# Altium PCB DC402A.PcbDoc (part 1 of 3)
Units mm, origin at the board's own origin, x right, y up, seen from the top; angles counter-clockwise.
Board outline 93 x 73 mm, 4 copper layers (Top Layer, Int1 (GND), Int2 (PWR), Bottom Layer), stack 1.369 mm thick; 244 components, 141 nets, 575 pads, 306 vias.
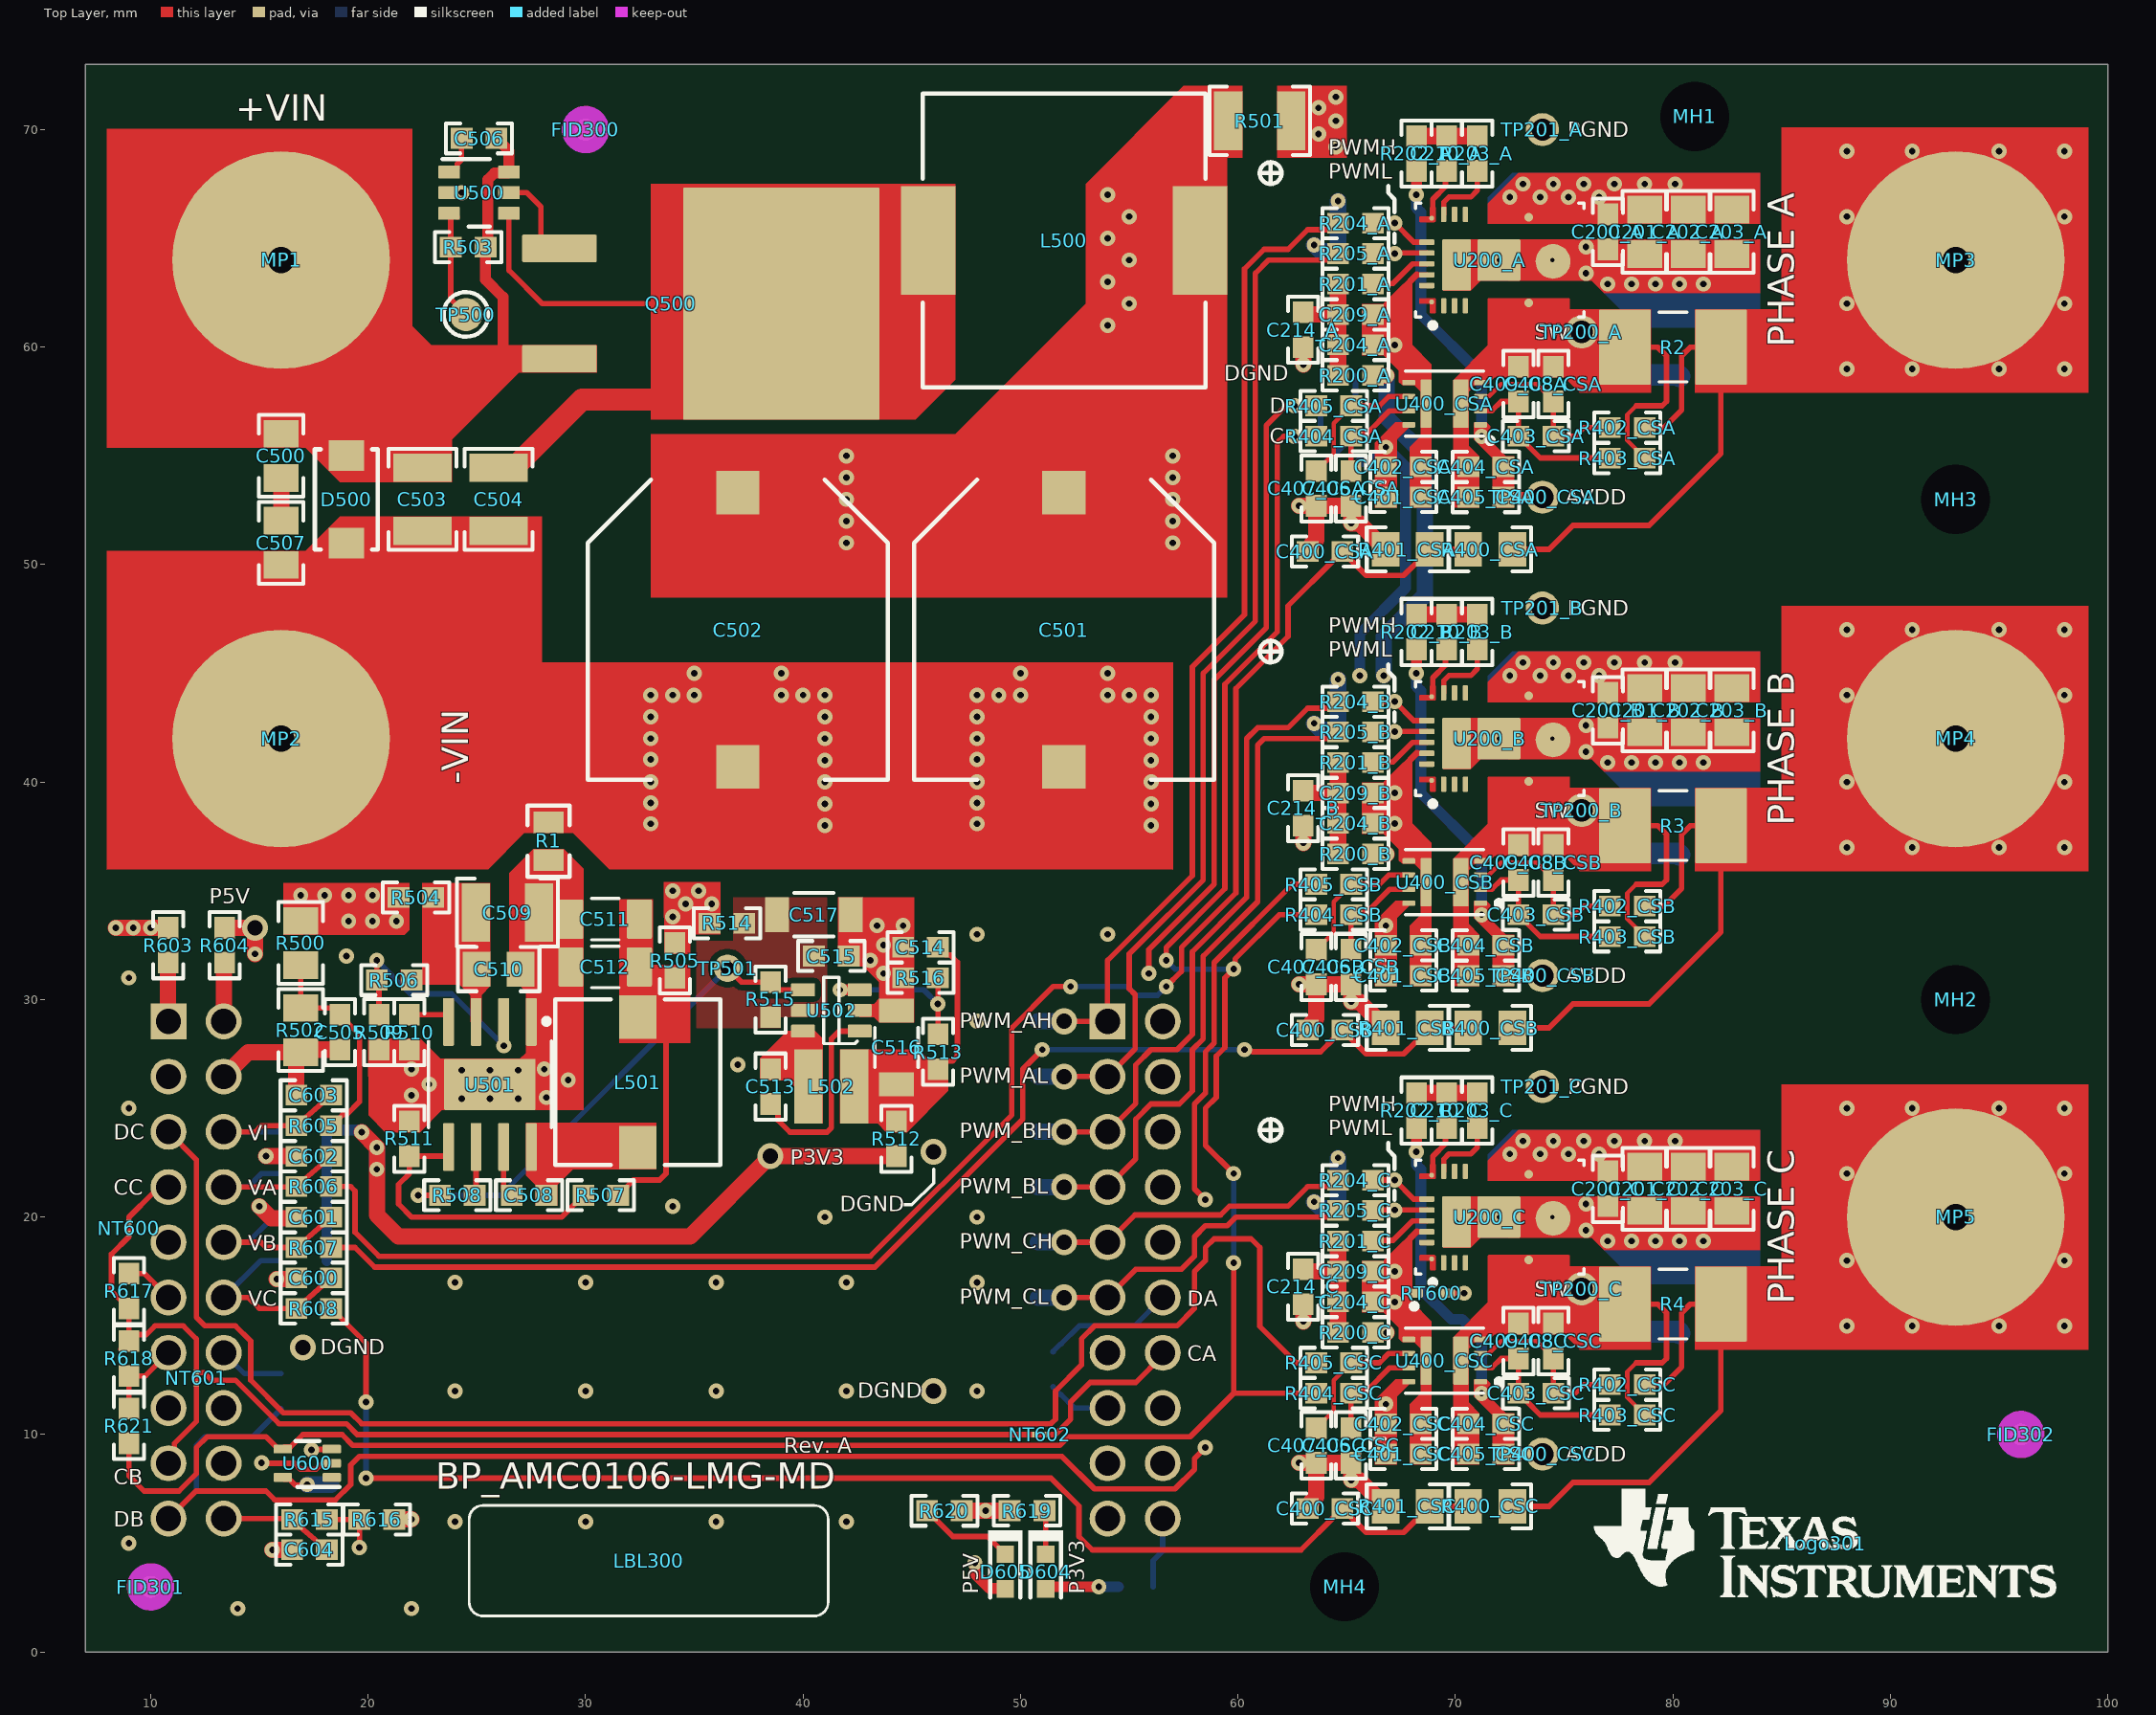
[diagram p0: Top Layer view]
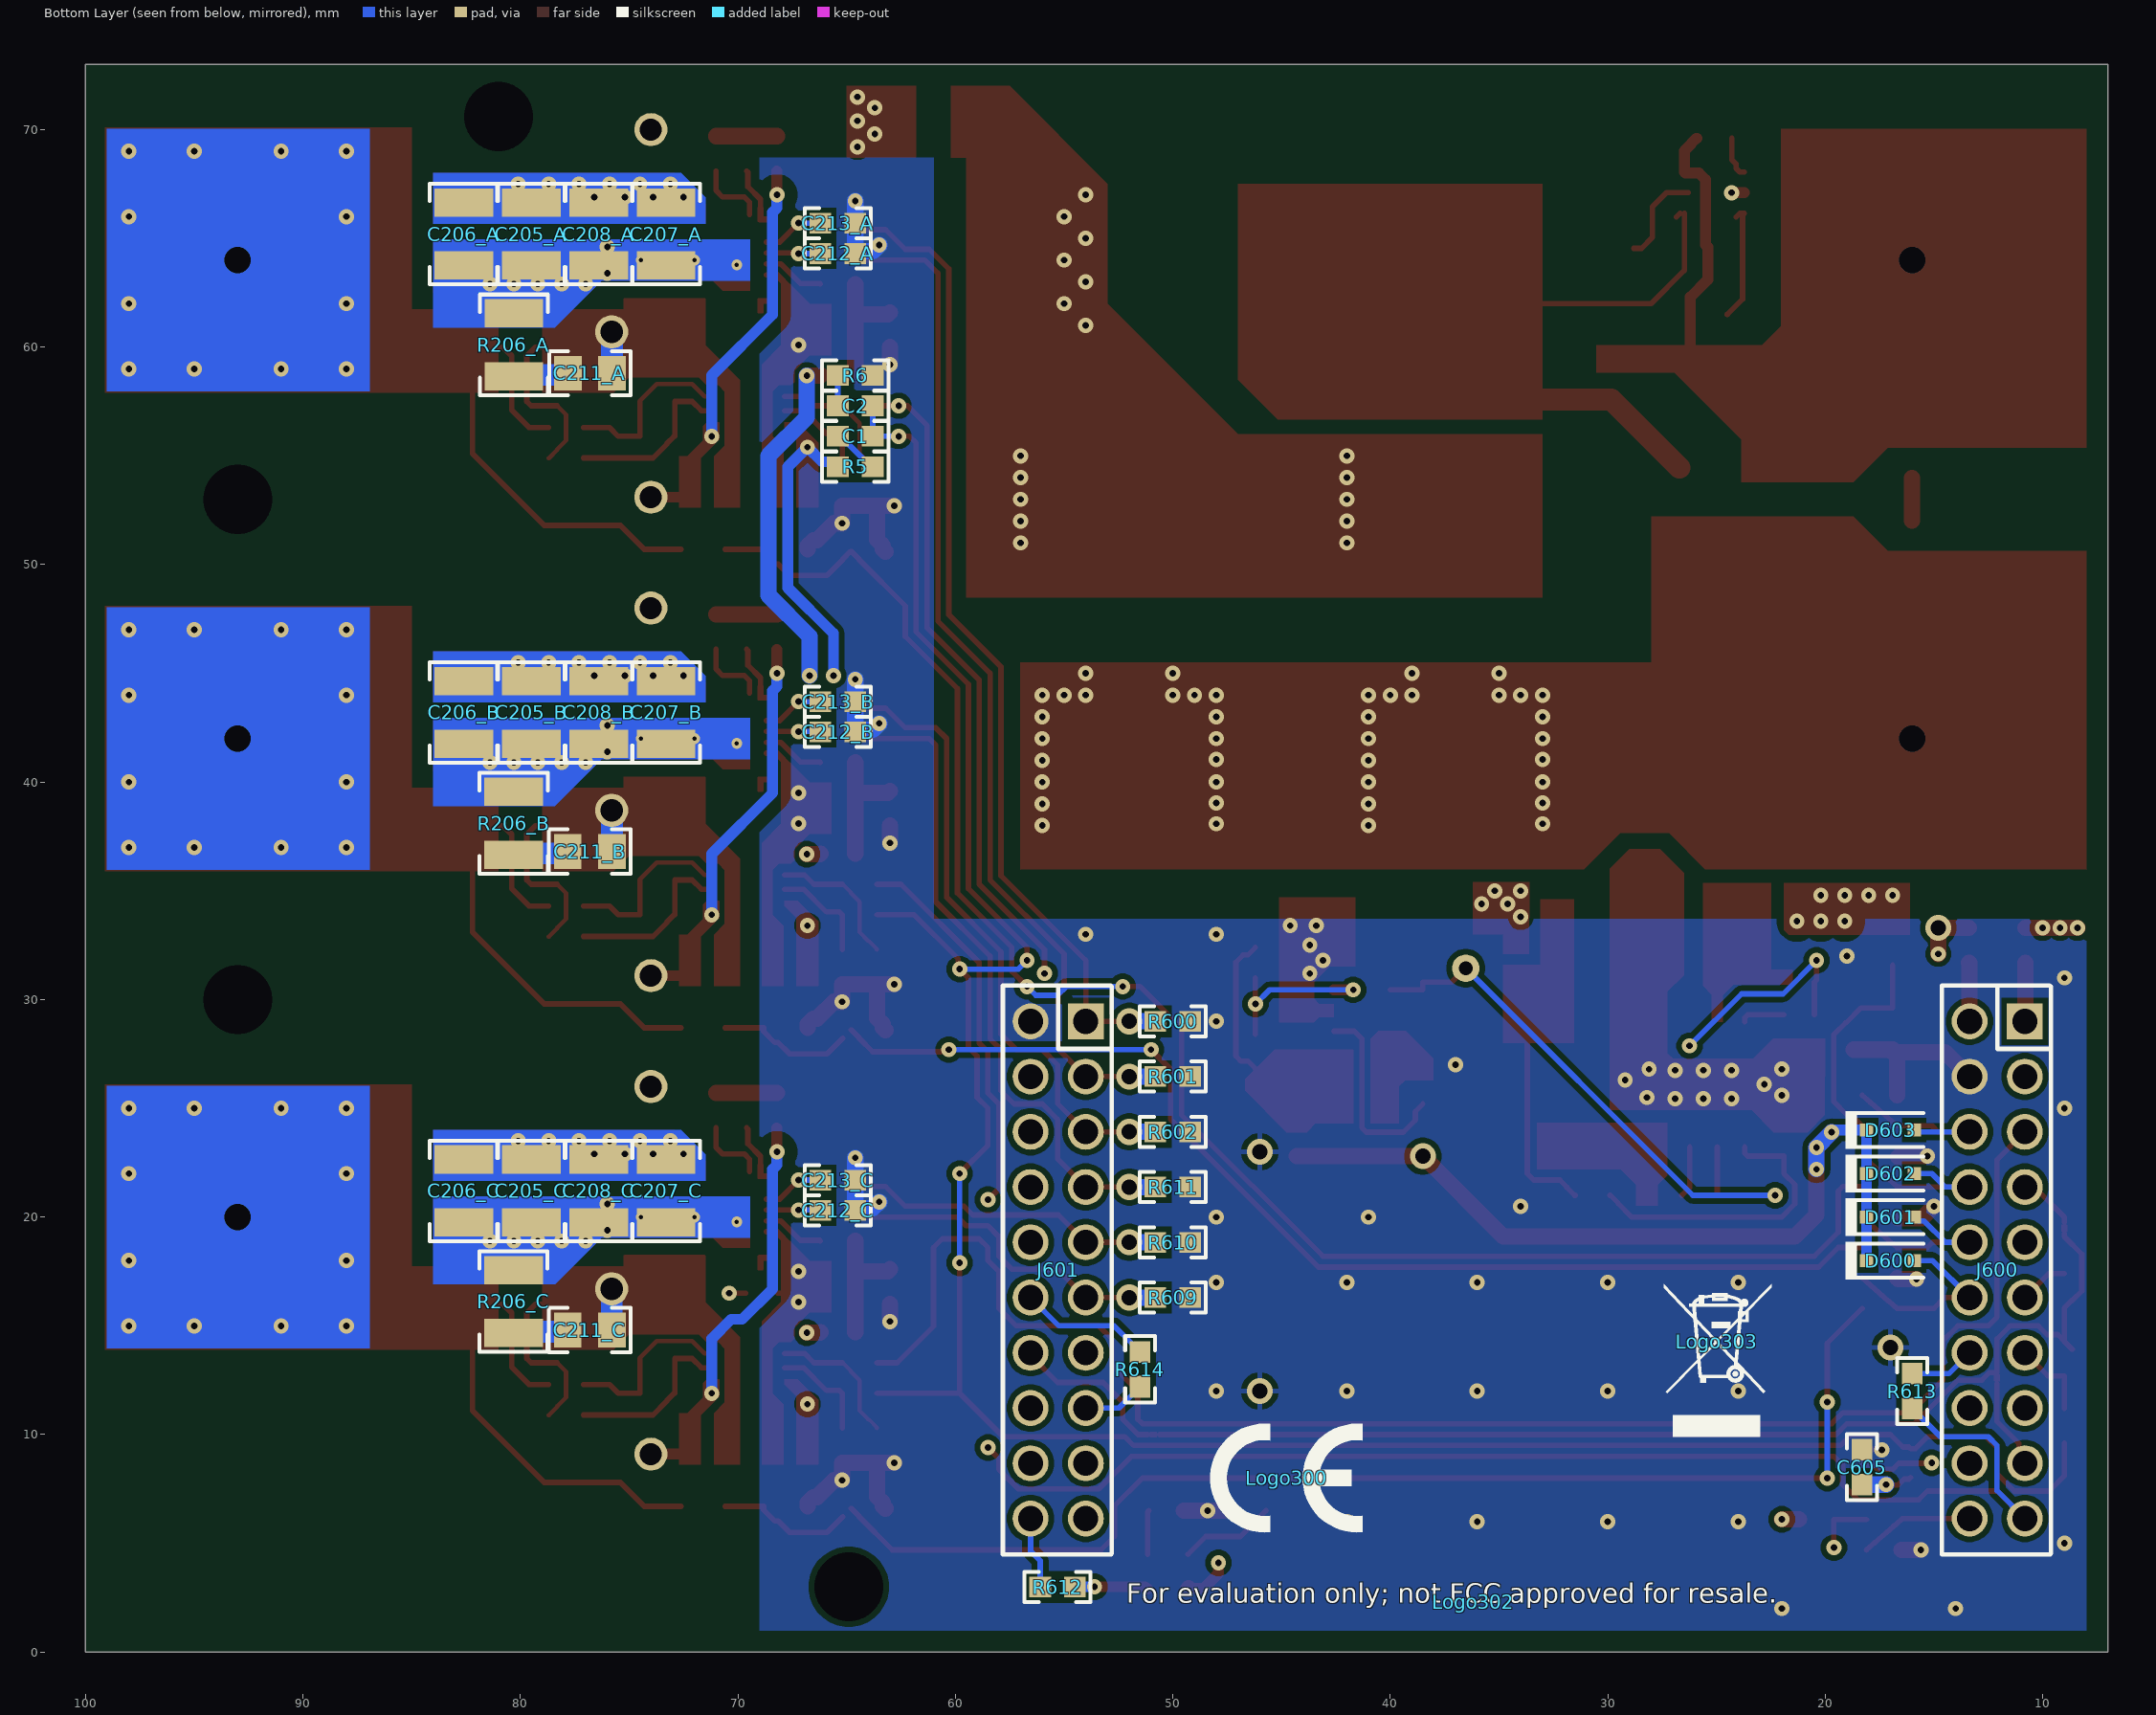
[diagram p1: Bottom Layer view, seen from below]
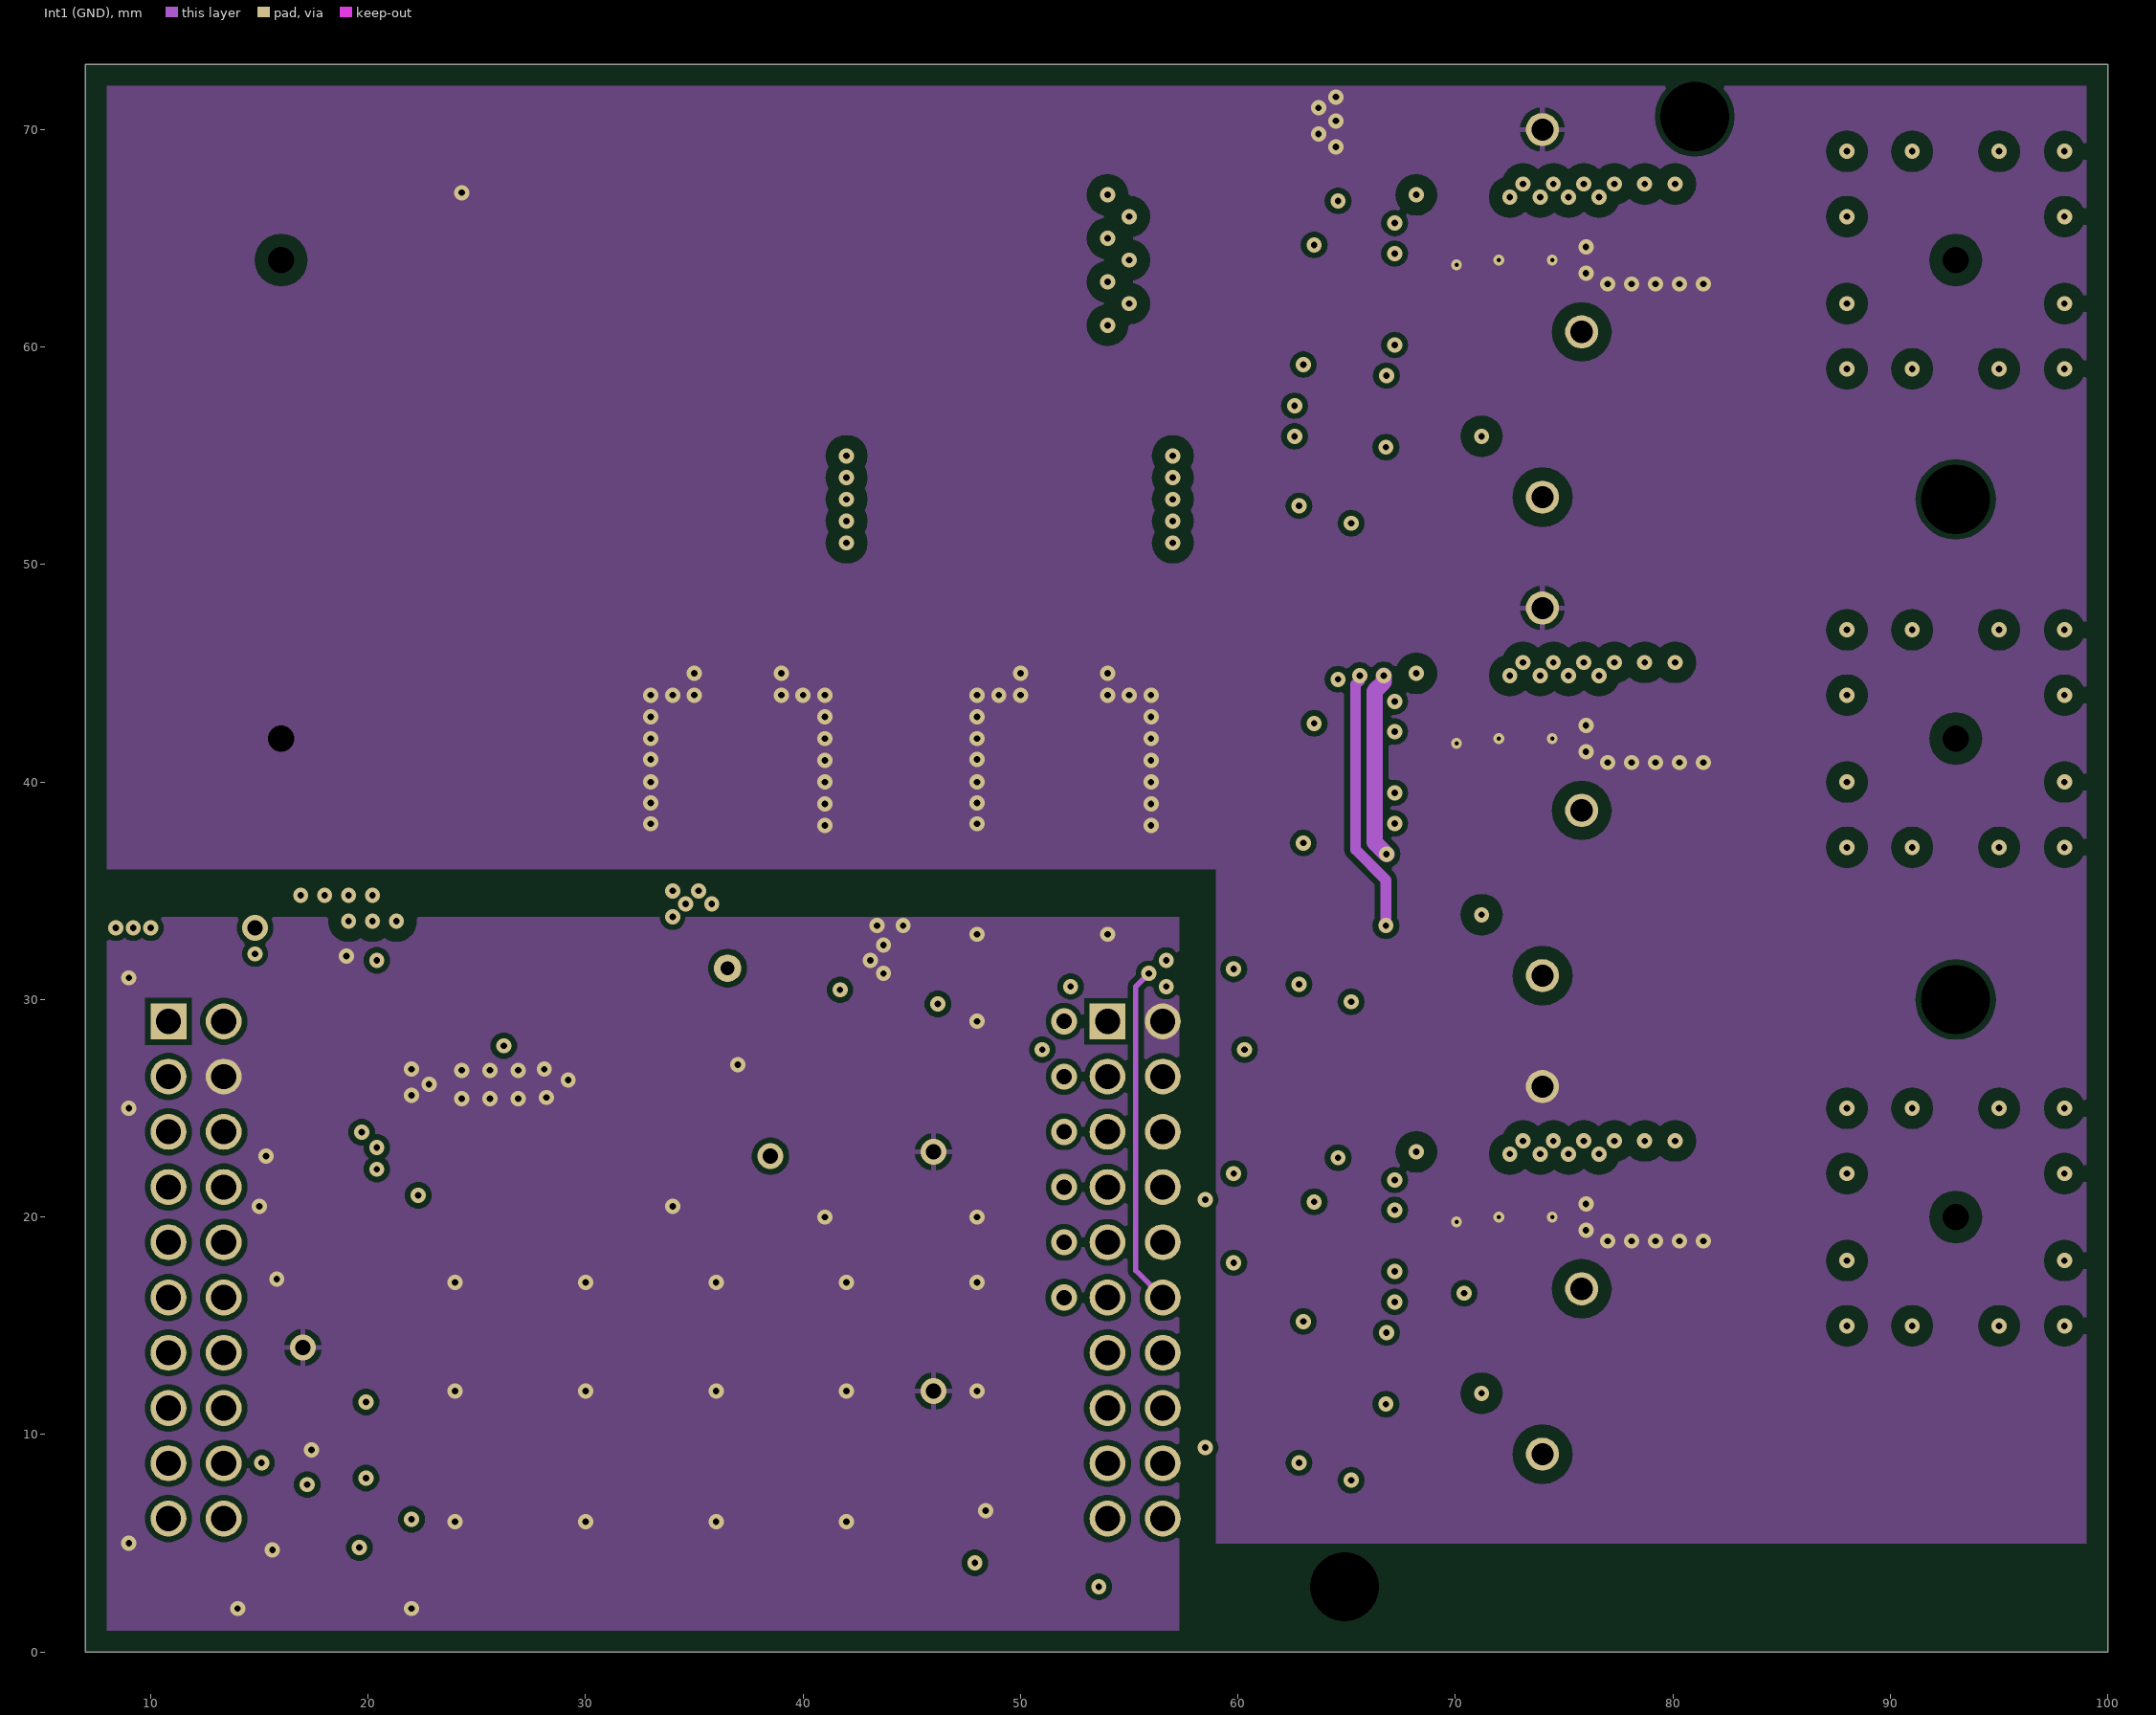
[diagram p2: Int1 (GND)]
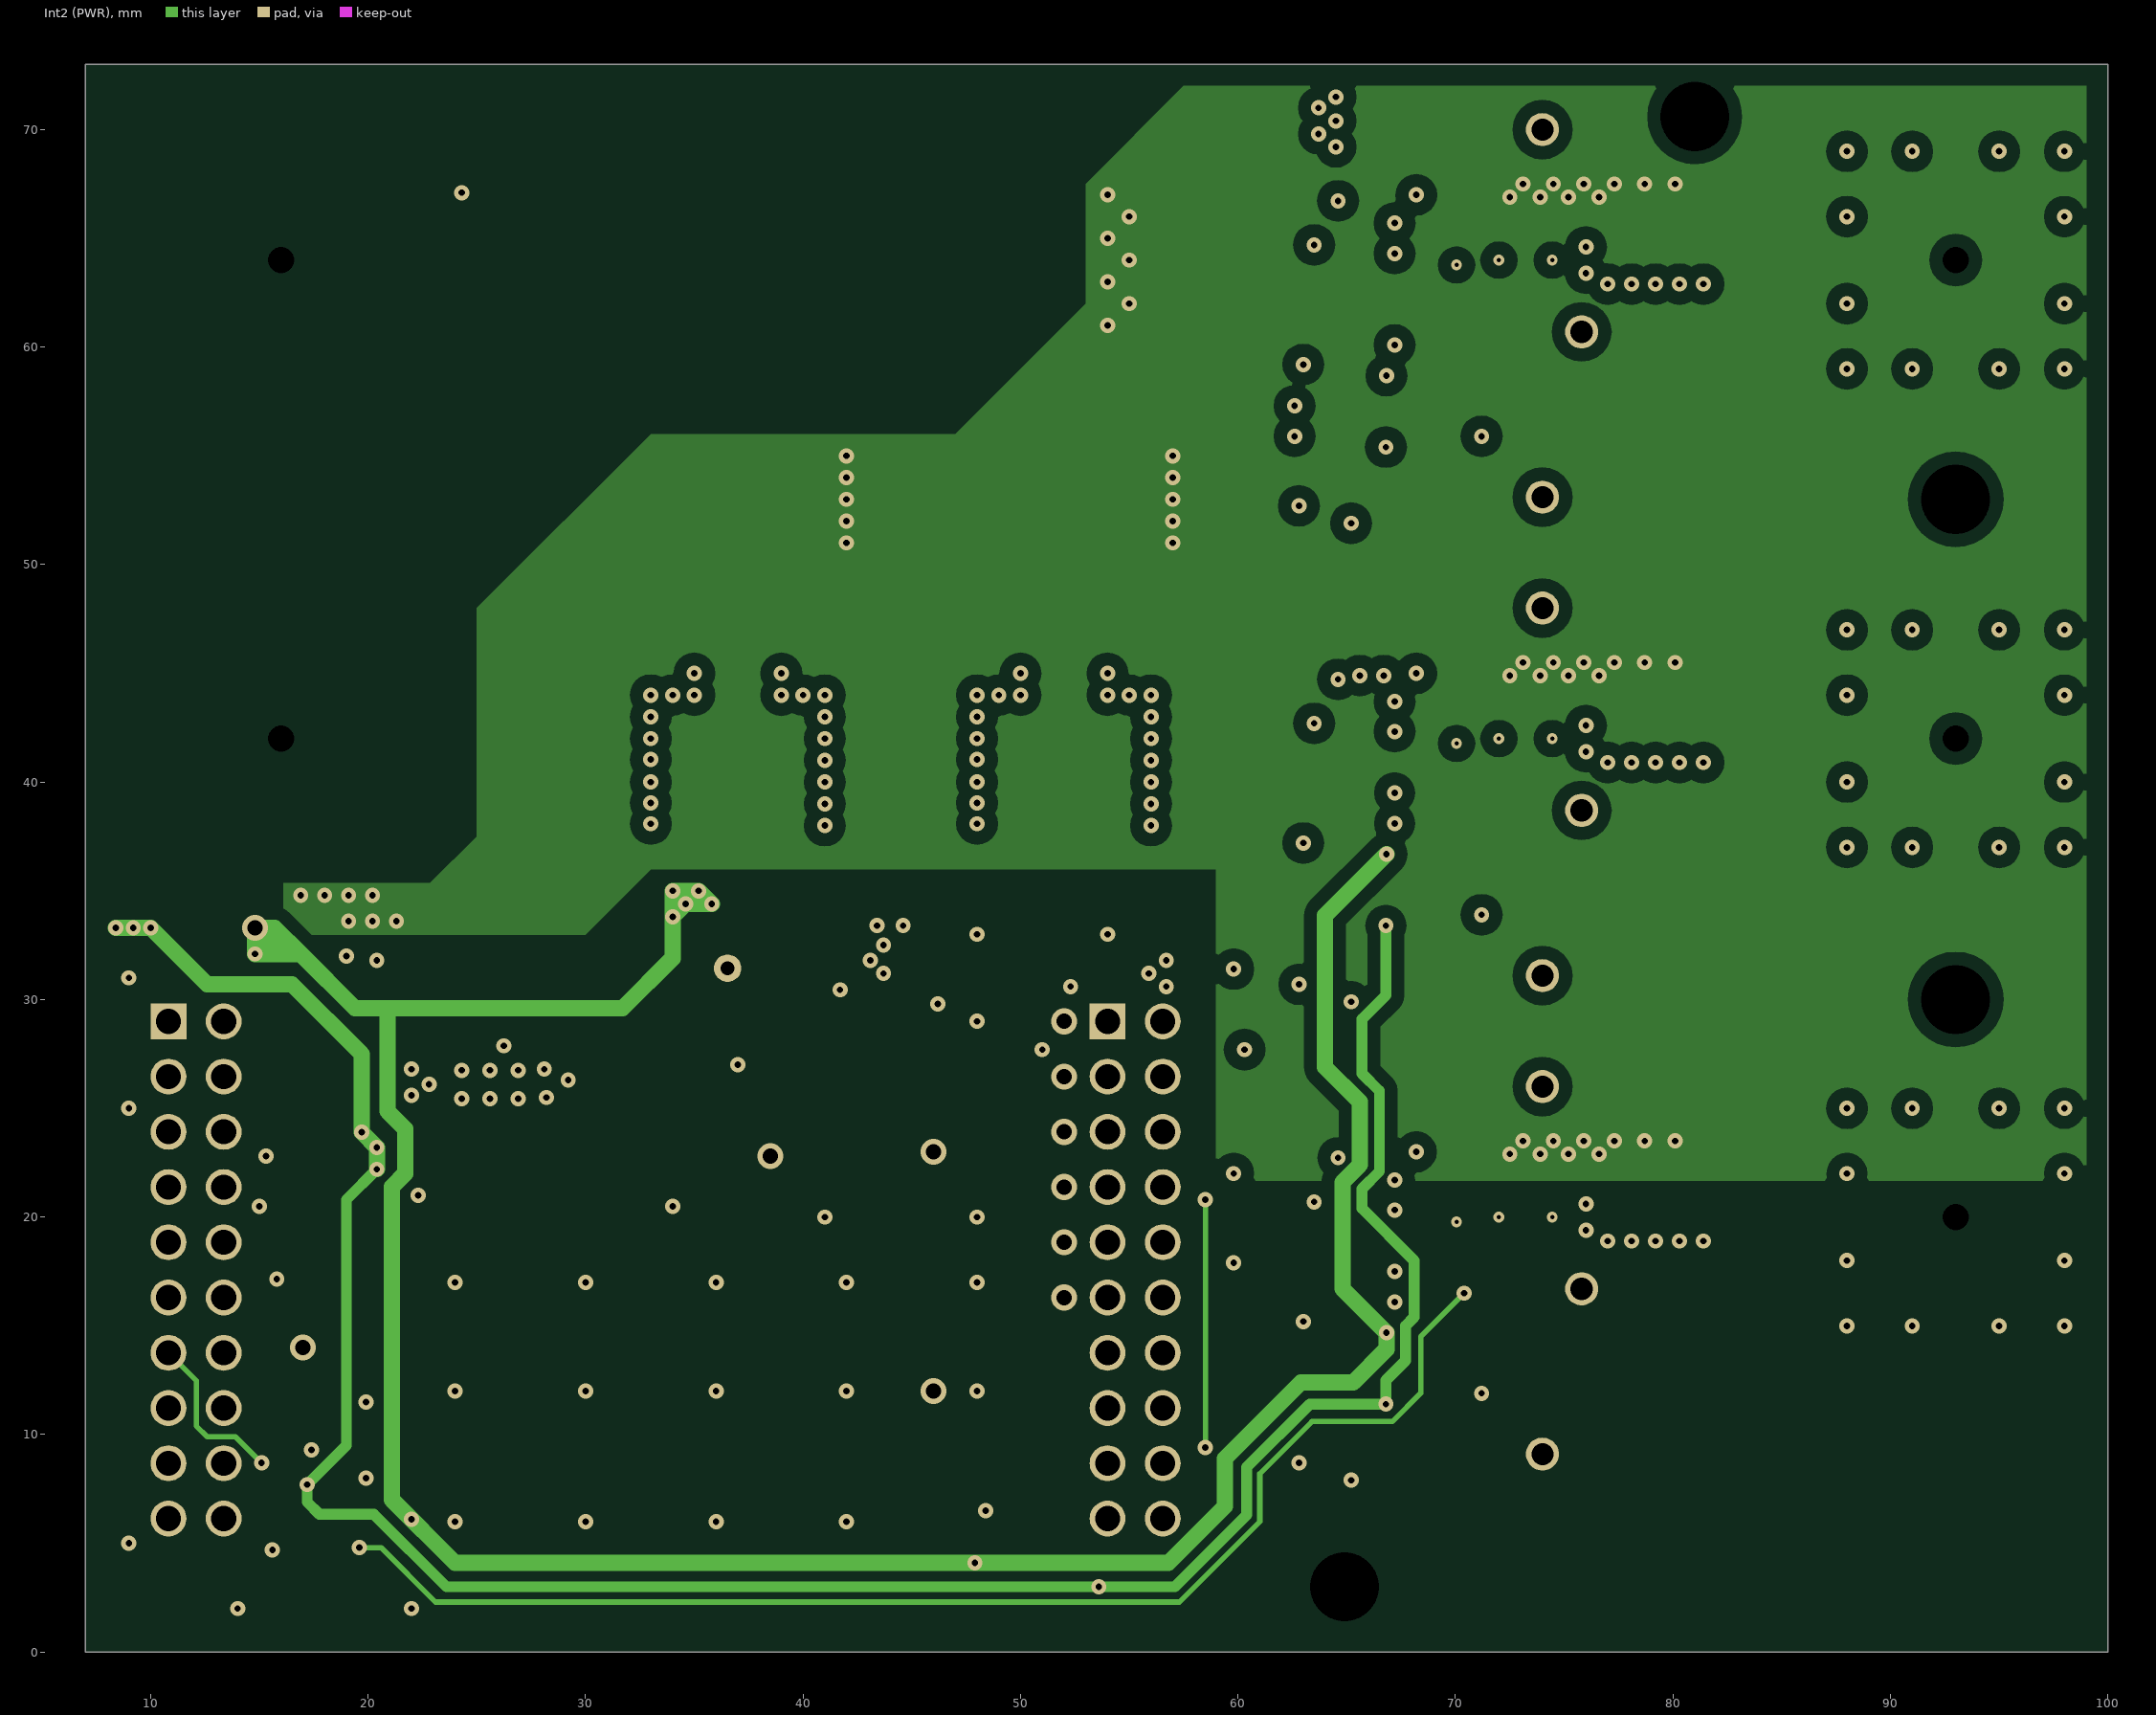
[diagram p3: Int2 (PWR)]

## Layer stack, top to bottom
Top Solder: solder mask 0.0254, SM-001, Dk 4
Top Layer: signal copper 0.035
Dielectric 1: prepreg 0.1295, PP-017, Dk 4.3
Dielectric 2: prepreg 0.1295, PP-017, Dk 4.3
Int1 (GND): signal copper 0.035
Dielectric 3: core 0.7112, Core-039, Dk 4.8
Int2 (PWR): signal copper 0.035
Dielectric 4: prepreg 0.1295, PP-017, Dk 4.3
Dielectric 5: prepreg 0.1295, PP-017, Dk 4.3
Bottom Layer: signal copper 0.035
Bottom Solder: solder mask 0.0254, SM-001, Dk 4

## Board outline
7,0 7,73 100,73 100,0

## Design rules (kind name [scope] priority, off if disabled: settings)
AcuteAngle [All] p1: minimum=4.50000000000000E+0001 checktracksonly=FALSE
AssemblyTestPointUsage [All] p1: valid=2
BoardOutlineClearance BoardOutlineClearance_MountingHoles [OnCopper and InComponentClass('Mounting Holes')] p1: gap=1 ignorepadtopadclearanceinfootprint=FALSE
BoardOutlineClearance BoardOutlineClearance_Poly [OnCopper and IsPoly] p2: gap=0.635 ignorepadtopadclearanceinfootprint=FALSE
BoardOutlineClearance [OnCopper and Not InComponentClass('Logo') and not InComponentClass('FiducialMark') and not InRegion(1000,500,4000,800) and not InPoly] p3: gap=0.8 ignorepadtopadclearanceinfootprint=FALSE
Clearance Clearance_RedCube [InComponent('J1') or InComponent('J2')] p1 off: gap=0 ignorepadtopadclearanceinfootprint=TRUE
Clearance Clearance_PWR [InNetClass('PWR') vs not InNetClass('PWR')] p2: gap=0.6 ignorepadtopadclearanceinfootprint=TRUE
Clearance Clearance_SW [InNetClass('SW') vs not InNetClass('SW')] p3: gap=0.6 ignorepadtopadclearanceinfootprint=TRUE
Clearance Clearance_Keepouts [((IsTrack Or IsArc) And Not InPoly) And IsFree and IsKeepOut vs ((IsTrack Or IsArc) And Not InPoly) And IsFree and IsKeepOut] p4: gap=0 ignorepadtopadclearanceinfootprint=FALSE
Clearance Clearance_Poly [InPolygon] p5: gap=0.25 ignorepadtopadclearanceinfootprint=TRUE
Clearance Clearance_FiducialMark [IsKeepOut and InComponentClass('FiducialMark') vs IsPad and InComponentClass('FiducialMark')] p6: gap=0 ignorepadtopadclearanceinfootprint=FALSE
Clearance [All] p7: gap=0.2 ignorepadtopadclearanceinfootprint=TRUE
ComponentClearance ComponentClearance_Testpoint [(HasFootprint('TP_50MIL-25MILHOLE') OR HasFootprint('TP_VIA_060RND040'))] p1: gap=0.2 collisioncheckmode=3 verticalgap=0.2 showdistances=FALSE
ComponentClearance ComponentClearance_MountingHoles_FiducialMarks [InComponentClass('Mounting Holes') vs InComponentClass('FiducialMark')] p2: gap=1.27 collisioncheckmode=3 verticalgap=0.254 showdistances=FALSE
ComponentClearance ComponentClearance_Shunt [InComponentClass('Header') vs InComponentClass('Shunt')] p3: gap=0 collisioncheckmode=3 verticalgap=0 showdistances=FALSE
ComponentClearance ComponentClearance_Logo [InComponentClass('Logo')] p4: gap=0.762 collisioncheckmode=3 verticalgap=0.254 showdistances=FALSE
ComponentClearance ComponentClearance_ScrewToNut [(HasFootprint('NY PMS 440 0025 PH')) vs (HasFootprint('Keystone_1902C'))] p5: gap=0.127 collisioncheckmode=3 verticalgap=0.254 showdistances=FALSE
ComponentClearance ComponentClearance_MountingHoles [InComponentClass('Mounting Holes')] p6: gap=2.54 collisioncheckmode=3 verticalgap=2540 showdistances=FALSE
ComponentClearance ComponentClearance_SmallPassives [HasFootprint('0201*') or HasFootprint('0402*') or HasFootprint('0508') or HasFootprint('0603*') or HasFootprint('0612') or HasFootprint('0805*') or HasFootprint('0815*') or HasFootprint('0830*') or HasFootprint('1206*') or HasFootprint('1210*') or HasFootprint('1808*') or HasFootprint('1812*') or HasFootprint('1825*') or HasFootprint('2010*') or HasFootprint('2220*') or HasFootprint('2225*') or HasFootprint('2512*') or HasFootprint('2728*') or HasFootprint('3518*') vs HasFootprint('0201*') or HasFootprint('0402*') or HasFootprint('0508') or HasFootprint('0603*') or HasFootprint('0612') or HasFootprint('0805*') or HasFootprint('0815*') or HasFootprint('0830*') or HasFootprint('1206*') or HasFootprint('1210*') or HasFootprint('1808*') or HasFootprint('1812*') or HasFootprint('1825*') or HasFootprint('2010*') or HasFootprint('2220*') or HasFootprint('2225*') or HasFootprint('2512*') or HasFootprint('2728*') or HasFootprint('3518*')] p7: gap=0.38 collisioncheckmode=3 verticalgap=0.254 showdistances=FALSE
ComponentClearance ComponentClearance_THtoSMT [IsThruComponent vs IsSMTComponent] p8: gap=0.762 collisioncheckmode=3 verticalgap=0.762 showdistances=FALSE
ComponentClearance ComponentClearance_THtoTH [IsThruComponent vs IsThruComponent] p9: gap=0.508 collisioncheckmode=3 verticalgap=0.762 showdistances=FALSE
ComponentClearance [All] p10: gap=0.508 collisioncheckmode=3 verticalgap=0.254 showdistances=FALSE
DiffPairsRouting [All] p1: maxlimit=2.54 minlimit=0.254 mostfreqgap=0.254 toplayer_minwidth=0.381 toplayer_maxwidth=0.381 toplayer_prefwidth=0.381 midlayer1_minwidth=0.381 midlayer1_maxwidth=0.381 midlayer1_prefwidth=0.381 midlayer2_minwidth=0.381 midlayer2_maxwidth=0.381 midlayer2_prefwidth=0.381 bottomlayer_minwidth=0.381 bottomlayer_maxwidth=0.381 bottomlayer_prefwidth=0.381 maxuncoupledlength=25.4
FabricationTestPointUsage TestPointUsage [All] p1: valid=2 allowmultiple=FALSE
FabricationTestpoint Testpoint [All] p1: side=3 testpointundercomponent=TRUE minsize=1.016 maxsize=2.54 preferedsize=1.524 minholesize=0 maxholesize=1.016 preferedholesize=0.813 testpointgrid=0.025 allowsidetop=TRUE allowsidebottom=TRUE usegrid=TRUE gridtolerance=0
FanoutControl Fanout_LCC [IsLCC] p1: bgadir=Out bgaviamode=Centered fanoutstyle=Auto fanoutdirection=Alternating viagrid=0.025 // Fanout_LCC (Default Rule)
FanoutControl Fanout_BGA [IsBGA] p2: bgadir=Out bgaviamode=Centered fanoutstyle=Auto fanoutdirection=Alternating viagrid=0.025 // Fanout_BGA (Default Rule)
FanoutControl Fanout_Default [All] p4: bgadir=Out bgaviamode=Centered fanoutstyle=Auto fanoutdirection=Alternating viagrid=0.025 // Fanout_Default (Default Rule)
FanoutControl Fanout_Small [(CompPinCount < 5)] p5: bgadir=Out bgaviamode=Centered fanoutstyle=Auto fanoutdirection=OutThenIn viagrid=0.025 // Fanout_Small (Default Rule)
HoleSize [All] p1: absolutevalues=TRUE maxlimit=6.375 minlimit=0.2 maxpercent=80.000 minpercent=20.000
MinimumAnnularRing MinimumAnnularRing_ThermalPadVias [IsVia and InAnyComponent] p1: minimumring=0.15
MinimumAnnularRing [All] p2: minimumring=0.2
MinimumSolderMaskSliver MinimumSolderMaskSliver_Logo [InComponentClass('Logo') vs InComponentClass('Logo')] p1: minsoldermaskwidth=0.018
MinimumSolderMaskSliver [All] p2: minsoldermaskwidth=0.1
PlaneClearance [All] p1: clearance=1
PlaneConnect [All] p1: planeconnectstyle=Relief reliefexpansion=0.254 reliefentries=4 reliefconductorwidth=0.254 reliefairgap=0.254
PolygonConnect [All] p1: connectstyle=Direct reliefconductorwidth=0.254 reliefentries=4 polygonreliefangle="90 Angle" airgapwidth=0.254
RoutingVias ThermalPadVias [IsVia and InAnyComponent] p1: holewidth=0.2 width=0.5 viastyle="Through Hole" minholewidth=0.2 minwidth=0.5 maxholewidth=0.33 maxwidth=0.7
RoutingVias [All] p2: holewidth=0.3 width=0.7 viastyle="Through Hole" minholewidth=0.3 minwidth=0.7 maxholewidth=0.7 maxwidth=1.2
SilkToBoardRegionClearance [Not ((IsComment or IsDesignator) And (Hide <> 'False')) and not InRegion(1000,500,4000,800)] p1:
SilkToSilkClearance SilkToSilkClearance_Pb-FreeLogo [(HasFootprint('Pb-Free_Overlay_Medium') OR HasFootprint('Pb-Free_Overlay_Small')) vs (HasFootprint('Pb-Free_Overlay_Medium') OR HasFootprint('Pb-Free_Overlay_Small'))] p1: silktosilkclearance=0
SilkToSilkClearance [All] p2: silktosilkclearance=0.1
SilkToSolderMaskClearance SilkToComponentPadClearance [(IsPad or IsFill or IsRegion) and InAnycomponent] p1: minsilkscreentomaskgap=0.127 clearancetoexposedcopper=TRUE
SilkToSolderMaskClearance "Silk to Solder Mask Opening" [All] p2: minsilkscreentomaskgap=0.1 clearancetoexposedcopper=FALSE
SolderMaskExpansion [All] p1: expansion=0.05 istentingtop=FALSE
UnRoutedNet [All] p1: checkbadconnections=TRUE
Width [All] p1: maxlimit=5 minlimit=0.152 preferedwidth=0.254 checkconnectedcopper=TRUE
13 further rules are at their usual default settings.

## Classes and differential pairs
channel class BP-AMC0106-LMG-MD-RevA_GaN-stage: A B C
channel class BP-AMC0106-LMG-MD-RevA_AMCsensing: CSA CSB CSC
net class SW: AVDD_CSA AVDD_CSB AVDD_CSC INN_CSA INN_CSB INN_CSC INP_CSA INP_CSB INP_CSC NetC210_A_1 NetC210_A_2 NetC210_B_1 NetC210_B_2 NetC210_C_1 NetC210_C_2 NetC403_CSA_1 NetC403_CSA_2 NetC403_CSB_1 NetC403_CSB_2 NetC403_CSC_1 NetC403_CSC_2 NetR203_A_2 NetR203_B_2 NetR203_C_2 NetU200_A_8 NetU200_A_9 NetU200_B_8 NetU200_B_9 NetU200_C_8 NetU200_C_9
net class PWR: NetC504_1 NetC509_1 NetQ500_1 VBUS VCC48
component class HW: !PCB300 FID300 FID301 FID302 LBL300 Logo300 Logo301 Logo302 Logo303 MH1 MH2 MH3 MH4 ZZ300 ZZ301 ZZ302 ZZ303
component class FLT: C500 C501 C502 C503 C504 C505 C506 C507 C508 C509 C510 C511 C512 C513 C514 C515 C516 C517 D500 L500 L501 L502 Q500 R500 R501 R502 R503 R504 R505 R506 R507 R508 R509 R510 R511 R512 R513 R514 R515 R516 TP500 TP501 U500 U501 U502
component class C: C200_C C201_C C202_C C203_C C204_C C205_C C206_C C207_C C208_C C209_C C210_C C211_C C212_C C213_C C214_C R200_C R201_C R202_C R203_C R204_C R205_C R206_C TP200_C TP201_C U200_C
component class CSC: C400_CSC C401_CSC C402_CSC C403_CSC C404_CSC C405_CSC C406_CSC C407_CSC C408_CSC C409_CSC R400_CSC R401_CSC R402_CSC R403_CSC R404_CSC R405_CSC TP400_CSC U400_CSC
component class CSB: C400_CSB C401_CSB C402_CSB C403_CSB C404_CSB C405_CSB C406_CSB C407_CSB C408_CSB C409_CSB R400_CSB R401_CSB R402_CSB R403_CSB R404_CSB R405_CSB TP400_CSB U400_CSB
component class CSA: C400_CSA C401_CSA C402_CSA C403_CSA C404_CSA C405_CSA C406_CSA C407_CSA C408_CSA C409_CSA R400_CSA R401_CSA R402_CSA R403_CSA R404_CSA R405_CSA TP400_CSA U400_CSA
component class CON: C600 C601 C602 C603 C604 C605 D600 D601 D602 D603 D604 D605 J600 J601 NT600 NT601 NT602 R600 R601 R602 R603 R604 R605 R606 R607 R608 R609 R610 R611 R612 R613 R614 R615 R616 R617 R618 R619 R620 R621 RT600 U600
component class B: C200_B C201_B C202_B C203_B C204_B C205_B C206_B C207_B C208_B C209_B C210_B C211_B C212_B C213_B C214_B R200_B R201_B R202_B R203_B R204_B R205_B R206_B TP200_B TP201_B U200_B
component class A: C200_A C201_A C202_A C203_A C204_A C205_A C206_A C207_A C208_A C209_A C210_A C211_A C212_A C213_A C214_A R200_A R201_A R202_A R203_A R204_A R205_A R206_A TP200_A TP201_A U200_A
component class Logo: Logo301
component class FiducialMark: FID300 FID301 FID302
component class AssemblyNote: ZZ300 ZZ301 ZZ302 ZZ303
component class Label: LBL300

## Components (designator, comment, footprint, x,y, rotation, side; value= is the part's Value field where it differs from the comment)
C1 "GRM1885C1H221JA01D" 0603 64.6,55.9 r0 bottom value=220pF
C2 "GRM1885C1H221JA01D" 0603 64.6,57.3 r180 bottom value=220pF
C200_A "GRM1885C2A102JA01D" 0603 77,65.3 r270 top locked value=1000pF (schematic designator C200)
C200_B "GRM1885C2A102JA01D" 0603 77,43.3 r270 top value=1000pF (schematic designator C200)
C200_C "GRM1885C2A102JA01D" 0603 77,21.3 r270 top value=1000pF (schematic designator C200)
C201_A "GRM21AR72A224KAC5L" 0805_HV 78.7,65.3 r270 top locked value=0.22uF (schematic designator C201)
C201_B "GRM21AR72A224KAC5L" 0805_HV 78.7,43.3 r270 top value=0.22uF (schematic designator C201)
C201_C "GRM21AR72A224KAC5L" 0805_HV 78.7,21.3 r270 top value=0.22uF (schematic designator C201)
C202_A "GRM21AR72A224KAC5L" 0805_HV 80.7,65.3 r270 top locked value=0.22uF (schematic designator C202)
C202_B "GRM21AR72A224KAC5L" 0805_HV 80.7,43.3 r270 top value=0.22uF (schematic designator C202)
C202_C "GRM21AR72A224KAC5L" 0805_HV 80.7,21.3 r270 top value=0.22uF (schematic designator C202)
C203_A "GRM21AR72A224KAC5L" 0805_HV 82.7,65.3 r270 top locked value=0.22uF (schematic designator C203)
C203_B "GRM21AR72A224KAC5L" 0805_HV 82.7,43.3 r270 top value=0.22uF (schematic designator C203)
C203_C "GRM21AR72A224KAC5L" 0805_HV 82.7,21.3 r270 top value=0.22uF (schematic designator C203)
C204_A "885012206095" 0603 65.4,60.1 r0 top locked value=0.1uF (schematic designator C204)
C204_B "885012206095" 0603 65.4,38.1 r0 top value=0.1uF (schematic designator C204)
C204_C "885012206095" 0603 65.4,16.1 r0 top value=0.1uF (schematic designator C204)
C205_A "CGA6M3X7S2A475K200AB" 1210_220 79.5,65.2 r270 bottom value=4.7uF (schematic designator C205)
C205_B "CGA6M3X7S2A475K200AB" 1210_220 79.5,43.2 r270 bottom value=4.7uF (schematic designator C205)
C205_C "CGA6M3X7S2A475K200AB" 1210_220 79.5,21.2 r270 bottom value=4.7uF (schematic designator C205)
C206_A "CGA6M3X7S2A475K200AB" 1210_220 82.6,65.2 r270 bottom value=4.7uF (schematic designator C206)
C206_B "CGA6M3X7S2A475K200AB" 1210_220 82.6,43.2 r270 bottom value=4.7uF (schematic designator C206)
C206_C "CGA6M3X7S2A475K200AB" 1210_220 82.6,21.2 r270 bottom value=4.7uF (schematic designator C206)
C207_A "CGA6M3X7S2A475K200AB" 1210_220 73.3,65.2 r270 bottom value=4.7uF (schematic designator C207)
C207_B "CGA6M3X7S2A475K200AB" 1210_220 73.3,43.2 r270 bottom value=4.7uF (schematic designator C207)
C207_C "CGA6M3X7S2A475K200AB" 1210_220 73.3,21.2 r270 bottom value=4.7uF (schematic designator C207)
C208_A "CGA6M3X7S2A475K200AB" 1210_220 76.4,65.2 r270 bottom value=4.7uF (schematic designator C208)
C208_B "CGA6M3X7S2A475K200AB" 1210_220 76.4,43.2 r270 bottom value=4.7uF (schematic designator C208)
C208_C "CGA6M3X7S2A475K200AB" 1210_220 76.4,21.2 r270 bottom value=4.7uF (schematic designator C208)
C209_A "CGA3E3X5R1A225K080AB" 0603 65.4,61.5 r0 top locked value=2.2uF (schematic designator C209)
C209_B "CGA3E3X5R1A225K080AB" 0603 65.4,39.5 r0 top value=2.2uF (schematic designator C209)
C209_C "CGA3E3X5R1A225K080AB" 0603 65.4,17.5 r0 top value=2.2uF (schematic designator C209)
C210_A "885012206095" 0603 69.6,68.9 r270 top locked value=0.1uF (schematic designator C210)
C210_B "885012206095" 0603 69.6,46.9 r270 top value=0.1uF (schematic designator C210)
C210_C "885012206095" 0603 69.6,24.9 r270 top value=0.1uF (schematic designator C210)
C211_A "GRM2165C2A271JA01D" 0805_HV 76.8,58.8 r0 bottom value=270pF (schematic designator C211)
C211_B "GRM2165C2A271JA01D" 0805_HV 76.808,36.808 r0 bottom value=270pF (schematic designator C211)
C211_C "GRM2165C2A271JA01D" 0805_HV 76.808,14.808 r0 bottom value=270pF (schematic designator C211)
C212_A "885012006052" 0603 65.4,64.3 r180 bottom value=15pF (schematic designator C212)
C212_B "885012006052" 0603 65.4,42.3 r180 bottom value=15pF (schematic designator C212)
C212_C "885012006052" 0603 65.4,20.3 r180 bottom value=15pF (schematic designator C212)
C213_A "885012006052" 0603 65.4,65.7 r180 bottom value=15pF (schematic designator C213)
C213_B "885012006052" 0603 65.4,43.7 r180 bottom value=15pF (schematic designator C213)
C213_C "885012006052" 0603 65.4,21.7 r180 bottom value=15pF (schematic designator C213)
C214_A "GRM188C81A106MA73D" 0603 63,60.8 r270 top value=10uF (schematic designator C214)
C214_B "GRM188C81A106MA73D" 0603 63,38.8 r270 top value=10uF (schematic designator C214)
C214_C "GRM188C81A106MA73D" 0603 63,16.8 r270 top value=10uF (schematic designator C214)
C400_CSA "GRM188R71C333KA01D" 0603 64,50.6 r180 top value=0.033uF (schematic designator C400)
C400_CSB "GRM188R71C333KA01D" 0603 64,28.6 r180 top value=0.033uF (schematic designator C400)
C400_CSC "GRM188R71C333KA01D" 0603 64,6.6 r180 top value=0.033uF (schematic designator C400)
C401_CSA "885012206095" 0603 67.6,53.1 r0 top locked value=0.1uF (schematic designator C401)
C401_CSB "885012206095" 0603 67.6,31.1 r0 top value=0.1uF (schematic designator C401)
C401_CSC "885012206095" 0603 67.6,9.1 r0 top value=0.1uF (schematic designator C401)
C402_CSA "GRM188Z71A475ME15D" 0603 67.6,54.5 r0 top locked value=4.7uF (schematic designator C402)
C402_CSB "GRM188Z71A475ME15D" 0603 67.6,32.5 r0 top value=4.7uF (schematic designator C402)
C402_CSC "GRM188Z71A475ME15D" 0603 67.6,10.5 r0 top value=4.7uF (schematic designator C402)
C403_CSA "GRM1885C1H103JA01D" 0603 73.7,55.9 r180 top locked value=0.01uF (schematic designator C403)
C403_CSB "GRM1885C1H103JA01D" 0603 73.7,33.9 r180 top value=0.01uF (schematic designator C403)
C403_CSC "GRM1885C1H103JA01D" 0603 73.7,11.9 r180 top value=0.01uF (schematic designator C403)
C404_CSA "GRM188Z71A475ME15D" 0603 71.4,54.5 r180 top locked value=4.7uF (schematic designator C404)
C404_CSB "GRM188Z71A475ME15D" 0603 71.4,32.5 r180 top value=4.7uF (schematic designator C404)
C404_CSC "GRM188Z71A475ME15D" 0603 71.4,10.5 r180 top value=4.7uF (schematic designator C404)
C405_CSA "885012206095" 0603 71.4,53.1 r180 top locked value=0.1uF (schematic designator C405)
C405_CSB "885012206095" 0603 71.4,31.1 r180 top value=0.1uF (schematic designator C405)
C405_CSC "885012206095" 0603 71.4,9.1 r180 top value=0.1uF (schematic designator C405)
C406_CSA "885012006052" 0603 65.2,53.5 r270 top locked value=15pF (schematic designator C406)
C406_CSB "885012006052" 0603 65.2,31.5 r270 top value=15pF (schematic designator C406)
C406_CSC "885012006052" 0603 65.2,9.5 r270 top value=15pF (schematic designator C406)
C407_CSA "885012006052" 0603 63.6,53.5 r270 top locked value=15pF (schematic designator C407)
C407_CSB "885012006052" 0603 63.6,31.5 r270 top value=15pF (schematic designator C407)
C407_CSC "885012006052" 0603 63.6,9.5 r270 top value=15pF (schematic designator C407)
C408_CSA "GRM1885C1H471JA01D" 0603 74.5,58.3 r90 top locked value=470pF (schematic designator C408)
C408_CSB "GRM1885C1H471JA01D" 0603 74.5,36.3 r90 top value=470pF (schematic designator C408)
C408_CSC "GRM1885C1H471JA01D" 0603 74.5,14.3 r90 top value=470pF (schematic designator C408)
C409_CSA "GRM1885C1H471JA01D" 0603 72.9,58.3 r90 top locked value=470pF (schematic designator C409)
C409_CSB "GRM1885C1H471JA01D" 0603 72.9,36.3 r90 top value=470pF (schematic designator C409)
C409_CSC "GRM1885C1H471JA01D" 0603 72.9,14.3 r90 top value=470pF (schematic designator C409)
C500 "GRM21AR72A224KAC5L" 0805_HV 16,55 r270 top value=0.22uF
C501 "UCZ1K151MNQ1MS" UCZ_1250x1350 52,47 r270 top value=150uF
C502 "UCZ1K151MNQ1MS" UCZ_1250x1350 37,47 r270 top value=150uF
C503 "CGA6M3X7S2A475K200AB" 1210_220 22.5,53 r270 top value=4.7uF
C504 "CGA6M3X7S2A475K200AB" 1210_220 26,53 r270 top value=4.7uF
C505 "GRM188R71C333KA01D" 0603 18.7,28.5 r270 top value=0.033uF
C506 "GRM188R61E105KA12D" 0603 25.1,69.6 r180 top value=1uF
C507 "GRM21AR72A224KAC5L" 0805_HV 16,51 r270 top value=0.22uF
C508 "885012206095" 0603 27.4,21 r0 top value=0.1uF
C509 "CGA6M3X7S2A475K200AB" 1210_220 26.4,34 r0 top value=4.7uF
C510 "GRM21AR72A224KAC5L" 0805_HV 26,31.4 r0 top value=0.22uF
C511 "GRM31CZ71C226ME15L" FP-GRM31CZ71C226ME15L_1206-MFG 30.9,33.7 r0 top value=22µF
C512 "GRM31CZ71C226ME15L" FP-GRM31CZ71C226ME15L_1206-MFG 30.9,31.5 r0 top value=22µF
C513 "885012206095" 0603 38.5,26 r90 top value=0.1uF
C514 "885012206095" 0603 45.4,32.4 r180 top value=0.1uF
C515 "885012206095" 0603 41.3,32 r0 top value=0.1uF
C516 "885012108022" 1206_180 44.3,27.8 r90 top value=10uF
C517 "885012108022" 1206_180 40.5,33.9 r0 top value=10uF
C600 "GRM1885C1H222JA01D" 0603 17.5,17.2 r180 top value=2200pF
C601 "GRM1885C1H222JA01D" 0603 17.5,20 r180 top value=2200pF
C602 "GRM1885C1H222JA01D" 0603 17.5,22.8 r180 top value=2200pF
C603 "GRM1885C1H222JA01D" 0603 17.5,25.6 r180 top value=2200pF
C604 "GRM1885C1H222JA01D" 0603 17.3,4.7 r180 top value=2200pF
C605 "885012206095" 0603 18.3,8.5 r90 bottom value=0.1uF
D500 "SMAJ64CA" SMA_Bi 19,53 r90 top value=64V
D600 "1N4148WS-7-F" SOD-323 17,18 r180 bottom value=75V
D601 "1N4148WS-7-F" SOD-323 17,20 r180 bottom value=75V
D602 "1N4148WS-7-F" SOD-323 17,22 r180 bottom value=75V
D603 "1N4148WS-7-F" SOD-323 17,24 r180 bottom value=75V
D604 "150060GS75000" WL-SMCW_GREEN 51.154,3.7 r270 top value=Green
D605 "150060RS75000" WL-SMCW_RED 49.3,3.7 r270 top value=Red
FID300 "Fiducial" Fiducial10-20 30,70 r90 top
FID301 "Fiducial" Fiducial10-20 10,3 r90 top
FID302 "Fiducial" Fiducial10-20 96,10 r90 top
J600 "CMP-0075442-1" CONN_SSW-110-23-F-D 12.09,17.57 r90 bottom
J601 "CMP-0075442-1" CONN_SSW-110-23-F-D 55.27,17.57 r90 bottom
L500 "744309047" WE-HCM_1390_L12.5W13H9 52,64.9 r0 top
L501 "7447789133" WE-PD_7332_PlasticBase 32.4,26.2 r90 top value=33uH
L502 "78438335047" WE-MAIA_3015 41.3,26 r0 top
LBL300 "THT-14-423-10" Label_650x200 32.9,4.2 r180 top
Logo300 "CE Mark" CE_Mark_5mm 44.775,8 r180 bottom
Logo301 "Texas Instruments" TI_Stacked_Overlay_Small 87,5 r0 top
Logo302 "FCC disclaimer" FCC_disclaimer 36.2,2.3 r180 bottom
Logo303 "WEEE logo" WEEE_Minimum 25,14.275 r180 bottom
MH1 "MTG_NoPads" NPTH125mil 81,70.6 r0 top
MH2 "MTG_NoPads" NPTH125mil 93,30 r0 top
MH3 "MTG_NoPads" NPTH125mil 93,53 r0 top
MH4 "MTG_NoPads" NPTH125mil 64.9,3 r0 top
MP1 "7466105" 7466105 16,64 r0 top
MP2 "7466105" 7466105 16,42 r0 top
MP3 "7466105" 7466105 93,64 r0 top
MP4 "7466105" 7466105 93,42 r0 top
MP5 "7466105" 7466105 93,20 r0 top
NT600 "Net-Tie" Net-Tie_10mil 9,19.492 r90 top net-tie
NT601 "Net-Tie" Net-Tie_10mil 12.1,12.6 r270 top net-tie
NT602 "Net-Tie" Net-Tie_10mil 50.9,10 r0 top net-tie
Q500 "STH310N10F7-2" DDPAK 35.05,62 r0 top value=100V
R1 "5106" 5106 28.3,37.3 r270 top value=0
R2 "ULRG32512R001FLFSLT" FP-ULRG32512R001FLFSLT_2512-MFG 80,60 r0 top locked value=1m
R3 "ULRG32512R001FLFSLT" FP-ULRG32512R001FLFSLT_2512-MFG 80,38 r0 top value=1m
R4 "ULRG32512R001FLFSLT" FP-ULRG32512R001FLFSLT_2512-MFG 80,16 r0 top value=1m
R5 "RC0603FR-07100RL" 0603 64.6,54.5 r180 bottom value=100
R6 "RC0603FR-07100RL" 0603 64.6,58.7 r180 bottom value=100
R200_A "RC0603JR-070RL" 0603 65.4,58.7 r180 top locked value=0 (schematic designator R200)
R200_B "RC0603JR-070RL" 0603 65.4,36.7 r180 top value=0 (schematic designator R200)
R200_C "RC0603JR-070RL" 0603 65.4,14.7 r180 top value=0 (schematic designator R200)
R201_A "RC0603FR-072R74L" 0603 65.4,62.9 r0 top locked value=2.74 (schematic designator R201)
R201_B "RC0603FR-072R74L" 0603 65.4,40.9 r0 top value=2.74 (schematic designator R201)
R201_C "RC0603FR-072R74L" 0603 65.4,18.9 r0 top value=2.74 (schematic designator R201)
R202_A "RC0603JR-070RL" 0603 68.2,68.9 r90 top locked value=0 (schematic designator R202)
R202_B "RC0603JR-070RL" 0603 68.2,46.9 r90 top value=0 (schematic designator R202)
R202_C "RC0603JR-070RL" 0603 68.2,24.9 r90 top value=0 (schematic designator R202)
R203_A "RC0603FR-072R74L" 0603 71,68.9 r270 top locked value=2.74 (schematic designator R203)
R203_B "RC0603FR-072R74L" 0603 71,46.9 r270 top value=2.74 (schematic designator R203)
R203_C "RC0603FR-072R74L" 0603 71,24.9 r270 top value=2.74 (schematic designator R203)
R204_A "RC0603FR-0710RL" 0603 65.4,65.7 r0 top locked value=10.0 (schematic designator R204)
R204_B "RC0603FR-0710RL" 0603 65.4,43.7 r0 top value=10.0 (schematic designator R204)
R204_C "RC0603FR-0710RL" 0603 65.4,21.7 r0 top value=10.0 (schematic designator R204)
R205_A "RC0603FR-0710RL" 0603 65.4,64.3 r0 top locked value=10.0 (schematic designator R205)
R205_B "RC0603FR-0710RL" 0603 65.4,42.3 r0 top value=10.0 (schematic designator R205)
R205_C "RC0603FR-0710RL" 0603 65.4,20.3 r0 top value=10.0 (schematic designator R205)
R206_A "RC1210FR-072R7L" 1210 80.3,60.1 r270 bottom value=2.70 (schematic designator R206)
R206_B "RC1210FR-072R7L" 1210 80.308,38.108 r270 bottom value=2.70 (schematic designator R206)
R206_C "RC1210FR-072R7L" 1210 80.316,16.116 r270 bottom value=2.70 (schematic designator R206)
R400_CSA "ERJ-6ENF1003V" 0805_HV 71.6,50.7 r180 top value=100k (schematic designator R400)
R400_CSB "ERJ-6ENF1003V" 0805_HV 71.6,28.7 r180 top value=100k (schematic designator R400)
R400_CSC "ERJ-6ENF1003V" 0805_HV 71.6,6.7 r180 top value=100k (schematic designator R400)
R401_CSA "ERJ-6ENF4221V" 0805_HV 67.8,50.7 r0 top value=4.22k (schematic designator R401)
R401_CSB "ERJ-6ENF4221V" 0805_HV 67.8,28.7 r0 top value=4.22k (schematic designator R401)
R401_CSC "ERJ-6ENF4221V" 0805_HV 67.8,6.7 r0 top value=4.22k (schematic designator R401)
R402_CSA "RC0603FR-0710RL" 0603 77.9,56.3 r0 top locked value=10.0 (schematic designator R402)
R402_CSB "RC0603FR-0710RL" 0603 77.9,34.3 r0 top value=10.0 (schematic designator R402)
R402_CSC "RC0603FR-0710RL" 0603 77.9,12.3 r0 top value=10.0 (schematic designator R402)
R403_CSA "RC0603FR-0710RL" 0603 77.9,54.9 r0 top locked value=10.0 (schematic designator R403)
R403_CSB "RC0603FR-0710RL" 0603 77.9,32.9 r0 top value=10.0 (schematic designator R403)
R403_CSC "RC0603FR-0710RL" 0603 77.9,10.9 r0 top value=10.0 (schematic designator R403)
R404_CSA "RC0603FR-0710RL" 0603 64.4,55.9 r0 top locked value=10.0 (schematic designator R404)
R404_CSB "RC0603FR-0710RL" 0603 64.4,33.9 r0 top value=10.0 (schematic designator R404)
R404_CSC "RC0603FR-0710RL" 0603 64.4,11.9 r0 top value=10.0 (schematic designator R404)
R405_CSA "RC0603FR-0710RL" 0603 64.4,57.3 r0 top locked value=10.0 (schematic designator R405)
R405_CSB "RC0603FR-0710RL" 0603 64.4,35.3 r0 top value=10.0 (schematic designator R405)
R405_CSC "RC0603FR-0710RL" 0603 64.4,13.3 r0 top value=10.0 (schematic designator R405)
R500 "ERJ-6ENF1003V" 0805_HV 16.9,32.6 r270 top value=100k
R501 "RC1210JR-0722KL" 1210 61,70.4 r180 top value=22k
R502 "ERJ-6ENF4221V" 0805_HV 16.9,28.6 r90 top value=4.22k
R503 "RC0603FR-07100KL" 0603 24.6,64.6 r0 top value=100k
R504 "PMR03EZPJ000" 0603 22.2,34.7 r180 top value=0
R505 "PMR03EZPJ000" 0603 34.1,31.8 r270 top value=0
R506 "RC0603FR-07100KL" 0603 21.2,30.9 r180 top value=100k
R507 "RC0603FR-0740K2L" 0603 30.7,21 r0 top value=40.2k
R508 "PMR03EZPJ000" 0603 24.1,21 r0 top value=0
R509 "RC0603FR-07100KL" 0603 20.5,28.5 r270 top value=100k
R510 "RC0603FR-0764K9L" 0603 21.9,28.5 r90 top value=64.9k
R511 "RC0603FR-0710KL" 0603 21.9,23.6 r270 top value=10.0k
R512 "PMR03EZPJ000" 0603 44.3,23.6 r90 top value=0
R513 "RC0603FR-0751KL" 0603 46.2,27.6 r270 top value=51.0k
R514 "PMR03EZPJ000" 0603 36.5,33.5 r180 top value=0
R515 "RC0603FR-07100KL" 0603 38.5,30 r270 top value=100k
R516 "RC0603FR-0722K1L" 0603 45.4,31 r0 top value=22.1k
R600 "RC0603FR-0710KL" 0603 50,29 r180 bottom value=10.0k
R601 "RC0603FR-0710KL" 0603 50,26.46 r180 bottom value=10.0k
R602 "RC0603FR-0710KL" 0603 50,23.92 r180 bottom value=10.0k
R603 "PMR03EZPJ000" 0603 10.8,32.5 r90 top value=0
R604 "PMR03EZPJ000" 0603 13.4,32.5 r270 top value=0
R605 "RC0603FR-0710RL" 0603 17.5,24.2 r0 top value=10.0
R606 "RC0603FR-0710RL" 0603 17.5,21.4 r0 top value=10.0
R607 "RC0603FR-0710RL" 0603 17.5,18.6 r0 top value=10.0
R608 "RC0603FR-0710RL" 0603 17.5,15.8 r0 top value=10.0
R609 "RC0603FR-0710KL" 0603 50,16.3 r0 bottom value=10.0k
R610 "RC0603FR-0710KL" 0603 50,18.84 r0 bottom value=10.0k
R611 "RC0603FR-0710KL" 0603 50,21.38 r0 bottom value=10.0k
R612 "RC0603FR-0710KL" 0603 55.3,3 r0 bottom value=10.0k
R613 "PMR03EZPJ000" 0603 16,12 r270 bottom value=0
R614 "PMR03EZPJ000" 0603 51.5,13 r270 bottom value=0
R615 "RC0603FR-0710RL" 0603 17.3,6.1 r0 top value=10.0
R616 "RC0603FR-0710KL" 0603 20.4,6.1 r0 top value=10.0k
R617 "PMR03EZPJ000" 0603 9,16.6 r270 top value=0
R618 "PMR03EZPJ000" 0603 9,13.5 r90 top value=0
R619 "RC0603FR-074K7L" 0603 50.3,6.5 r0 top value=4.70k
R620 "RC0603FR-071K6L" 0603 46.5,6.5 r180 top value=1.60k
R621 "PMR03EZPJ000" 0603 9,10.4 r270 top value=0
RT600 "TMP6131DYAT" DYA0002A-MFG 68.9,16.5 r0 top value=10k
TP200_A "TESTPOINT" TP_VIA_060RND040 75.8,60.7 r90 top locked (schematic designator TP200)
TP200_B "TESTPOINT" TP_VIA_060RND040 75.8,38.7 r90 top (schematic designator TP200)
TP200_C "TESTPOINT" TP_VIA_060RND040 75.8,16.7 r90 top (schematic designator TP200)
TP201_A "TESTPOINT" TP_VIA_060RND040 74,70 r90 top locked (schematic designator TP201)
TP201_B "TESTPOINT" TP_VIA_060RND040 74,48 r90 top (schematic designator TP201)
TP201_C "TESTPOINT" TP_VIA_060RND040 74,26 r90 top (schematic designator TP201)
TP400_CSA "TESTPOINT" TP_VIA_060RND040 74,53.1 r90 top locked (schematic designator TP400)
TP400_CSB "TESTPOINT" TP_VIA_060RND040 74,31.1 r90 top (schematic designator TP400)
TP400_CSC "TESTPOINT" TP_VIA_060RND040 74,9.1 r90 top (schematic designator TP400)
TP500 "TESTPOINT" TP_60MIL-SMT 24.5,61.5 r0 top
TP501 "TESTPOINT" TP_50MIL-25MILHOLE 36.527,31.441 r0 top
U200_A "LMG2100R026VBNR" VBN0016A-MFG 72.032,64 r90 top locked (schematic designator U200)
U200_B "LMG2100R026VBNR" VBN0016A-MFG 72.032,42 r90 top (schematic designator U200)
U200_C "LMG2100R026VBNR" VBN0016A-MFG 72.032,20 r90 top (schematic designator U200)
U400_CSA "AMC0106DENR" DEN0008A-MFG 69.5,57.4 r180 top (schematic designator U400)
U400_CSB "AMC0106DENR" DEN0008A-MFG 69.5,35.4 r180 top (schematic designator U400)
U400_CSC "AMC0106DENR" DEN0008A-MFG 69.5,13.4 r180 top (schematic designator U400)
U500 "LM74700QDBVRQ1" DBV0006A_N 25.1,67.1 r0 top
U501 "LMR38010FDDAR" DDA0008E-MFG 25.6,26.1 r270 top
U502 "LMR50410YFQDBVRQ1" DBV0006A-MFG 41.3,29.5 r180 top
U600 "SN74LVC1G17QDCKRQ1" DCK0005A_N 17.2,8.68 r180 top
ZZ300 "This Assembly Note is for PCB labels only" AssemblyNoteLabel 3,186 r0 top
ZZ301 "These assemblies are ESD sensitive, ESD precautions shall be observed." AssemblyNote 3,190 r0 top
ZZ302 "These assemblies must be clean and free from flux and all contaminants. Use of no clean flux is not acceptable." AssemblyNote 3,194 r0 top
ZZ303 "These assemblies must comply with workmanship standards IPC-A-610 Class 2, unless otherwise specified." AssemblyNote 3,198 r0 top

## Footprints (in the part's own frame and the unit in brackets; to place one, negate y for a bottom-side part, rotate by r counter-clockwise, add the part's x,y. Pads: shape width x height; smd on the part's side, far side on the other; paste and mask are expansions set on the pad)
0603 [mm] "0603 from SM-752 data"
  rect 1x0.95 smd: 1(-0.8,0) 2(0.8,0)
  silkscreen extent -1.52,-0.69 1.52,0.69, body extent -0.87,-0.47 0.87,0.47, height 1
0805_HV [mil] "0805 with 30mil clearance between pads"
  rect 50x63 smd: 1(-40,0) 2(40,0)
  silkscreen extent -74,-40 74,40, body extent -43,-29 43,29, height 57
1206_180 [mm] "1206_180"
  rect 1.1x1.6 smd: 1(-1.7,0) 2(1.7,0)
  silkscreen extent -0.9,-1 0.9,1, body extent -1.75,-0.95 1.75,0.95, height 1.8
1210 [mm] "1210 from SM-752 data"
  rect 1.3x2.7 smd: 1(-1.45,0) 2(1.45,0)
  silkscreen extent -2.32,-1.57 2.32,1.57, body extent -1.7,-1.35 1.7,1.35, height 1.35
1210_220 [mm] "1210"
  rect 1.3x2.7 smd: 1(-1.45,0) 2(1.45,0)
  silkscreen extent -2.32,-1.57 2.32,1.57, body extent -1.7,-1.35 1.7,1.35, height 2.2
5106 [mm] "Keystone"
  rect 0.99x1.4 smd: 1(-0.85,0) 2(0.88,0)
  silkscreen extent -1.63,-0.97 1.65,0.97, body extent -1.06,-0.69 1.06,0.69, height 0.84
7466105 [mm] "SMD with internal blind-hole thread with Pin, M5 - 4 mm"
  round 10 / inner round 0 / far side round 0 hole 1.2 unplated: 1(0,0)
  body extent -4.5,-4.5 4.5,4.5, height 7
AssemblyNote [mm] "Assembly Note"
AssemblyNoteLabel [mm] "Assembly Note for PCB Labels"
CE_Mark_5mm [mm] "Minimum text height for CE Mark"
  silkscreen extent -3.5,-2.5 3.5,2.5
CONN_SSW-110-23-F-D [mm] "SAMTEC"
  rect 1.65x1.65 hole 1.15: 1(11.43,-1.27)
  round 1.65 hole 1.15: 2(11.43,1.27) 3(8.89,-1.27) 4(8.89,1.27) 5(6.35,-1.27) 6(6.35,1.27) 7(3.81,-1.27) 8(3.81,1.27) 9(1.27,-1.27) 10(1.27,1.27) 11(-1.27,-1.27) 12(-1.27,1.27) 13(-3.81,-1.27) 14(-3.81,1.27) 15(-6.35,-1.27) 16(-6.35,1.27) 17(-8.89,-1.27) 18(-8.89,1.27) 19(-11.43,-1.27) 20(-11.43,1.27)
  silkscreen extent -13.08,-2.46 13.08,2.54, body extent -13,-2.51 13,2.54, height 8.59
DBV0006A-MFG [mm]
  rrect17% 1.1x0.6 smd paste+0 mask+0: 1(-1.3,0.95) 2(-1.3,0) 3(-1.3,-0.95) 4(1.3,-0.95) 5(1.3,0) 6(1.3,0.95)
  silkscreen extent -0.35,-1.53 0.35,1.53, body extent -1.95,-1.78 1.95,1.78, height 0.25
DBV0006A_N [mm] "SOT23, 6-Leads, Body 2.9x1.6mm, Pitch 0.95mm, Lead Span 2.8mm, IPC Medium Density"
  rrect17% 1x0.6 smd: 1(-1.375,0.95) 2(-1.375,0) 3(-1.375,-0.95) 4(1.375,-0.95) 5(1.375,0) 6(1.375,0.95)
  silkscreen extent -1.68,-1.55 0.5,1.55, body extent -1.42,-1.46 1.42,1.46, height 1.12
DCK0005A_N [mm] "SOT353, 5-Leads, Body 2x1.3mm, Pitch 0.65mm, Lead Span 2.1mm, IPC Medium Density"
  rrect25% 0.85x0.4 smd: 1(-1.125,0.65) 2(-1.125,0) 3(-1.125,-0.65) 4(1.125,-0.65) 5(1.125,0.65)
  silkscreen extent -1.48,-1.02 0.55,1.1, body extent -1.14,-1 1.14,1, height 0.95
DDA0008E-MFG [mm]
  rrect20% 2.2x0.5 smd paste-1000 mask+0: 1(-2.875,1.905) 2(-2.875,0.635) 3(-2.875,-0.635) 4(-2.875,-1.905) 5(2.875,-1.905) 6(2.875,-0.635) 7(2.875,0.635) 8(2.875,1.905)
  rrect3% 2.35x4.2 smd paste-1000 mask-1000: 9(0,0)
  silkscreen extent -3.02,-2.83 2,2.83, body extent -4.08,-2.68 4.08,2.68, height 0.25
DDPAK [mil] "D2-PAK, 3-Pads, Body 9.7x10.4mm (max), TO-263AB, using Vishay Silionix recommended pad sizes"
  rrect8% 135x49.49 smd: 1(-246.06,100) 3(-246.06,-100)
  rrect1% 355x420 smd paste-181.1: 2(155.51,0)
  body extent -295,-202 324,202, height 180
DEN0008A-MFG [mm]
  rrect40% 0.6x0.25 smd paste+0 mask+0: 1(-1.65,0.975) 2(-1.65,0.325) 3(-1.65,-0.325) 4(-1.65,-0.975) 5(1.65,-0.975) 6(1.65,-0.325) 7(1.65,0.325) 8(1.65,0.975)
  rrect14% 0.7x2.23 smd paste-1000 mask+0: 4(-0.75,0)
  rrect20% 0.5x2.23 smd paste-1000 mask+0: 5(0.85,0)
  silkscreen extent -2.22,-1.5 1.8,1.82, body extent -2.05,-1.5 2.05,1.5, height 0.25
DYA0002A-MFG [mm]
  rrect25% 0.67x0.4 smd paste+0 mask+0: 1(-0.74,0) 2(0.74,0)
  silkscreen extent -0.92,-0.72 -0.67,-0.48, body extent -1.17,-0.67 1.17,0.67, height 0.25
FCC_disclaimer [mm]
Fiducial10-20 [mm]
  round 1 smd mask+0.5: 1(0,0)
  Top Layer keep-out circle w1.178: c0,0 r0.5
FP-GRM31CZ71C226ME15L_1206-MFG [mm] "Recommended Land Pattern"
  rrect9% 1.15x1.8 smd paste+0 mask+0: 1(-1.575,0) 2(1.575,0)
  silkscreen extent -0.63,-0.95 0.63,0.95, body extent -2.25,-1.05 2.25,1.05, height 0.25
FP-ULRG32512R001FLFSLT_2512-MFG [mm]
  rrect4% 2.38x3.45 smd paste+0 mask+0: 1(-2.21,0) 2(2.21,0)
  silkscreen extent -0.64,-1.6 0.64,1.6, body extent -3.5,-1.83 3.5,1.83, height 0.25
Label_650x200 [mil] "Thermal Transfer Label"
  round 1 on Mech13: 0(0,0)
  silkscreen extent -325,-100 325,100, body extent -325,-100 325,100, height 1
Net-Tie_10mil [mil] "10mil net tie, no solder mask opening, no solder paste"
  rect 10x10 smd paste-5 mask-5: 1(-10,0) 2(10,0)
  Top Layer region: -6,5 6,5 6,-5 -6,-5
NPTH125mil [mil]
  round 120 hole 125 unplated mask+15: 1(0,0)
SMA_Bi [mm] "SMD, 2-Leads, Body 4.275x2.575mm"
  rect 1.4x1.64 smd: 1(-2.015,0) 2(2.015,0)
  silkscreen extent -2.3,-1.45 2.3,1.45, body extent -2.52,-1.45 2.52,1.45, height 2.65
SOD-323 [mm] "NXP recommended land pattern"
  rect 0.6x0.6 smd paste-0.05: 1(-1.1,0) 2(1.1,0)
  silkscreen extent -2.06,-0.86 1.53,0.86, body extent -1.3,-0.67 1.3,0.68, height 1.1
TI_Stacked_Overlay_Small [mm]
  silkscreen extent -10.63,-2.49 10.63,2.49
TP_50MIL-25MILHOLE [mm]
  round 1.27 hole 0.635: 1(0,0)
TP_60MIL-SMT [mil]
  round 60 smd paste-30: 1(0,0)
  silkscreen extent -40,-40 41,40
TP_VIA_060RND040 [mil] "TP_VIA_060RND040"
  round 60 hole 40: 1(0,0)
UCZ_1250x1350 [mm] "SMD, 2-Leads, Dia 12.5mm"
  rect 2x2 smd: 1(-6.3,0) 2(6.3,0)
  Top Layer region: 8.8,-3.5 8.8,3.5 3.8,3.5 3.8,1 1.5,1 1.5,-1 3.8,-1 3.8,-3.5
  Top Layer region: -8.8,-3.5 -8.8,3.5 -3.8,3.5 -3.8,1 -1.5,1 -1.5,-1 -3.8,-1 -3.8,-3.5
  silkscreen extent -6.9,-6.9 6.9,6.9, body extent -6.9,-6.9 6.9,6.9, height 14.51
VBN0016A-MFG [mm]
  round 0.228 smd paste+0 mask+0: 1(-1.925,3.125) 11(1.925,3.125)
  rrect40% 0.7x0.25 smd paste+0 mask+0: 2(-2.1,2.575) 3(-2.1,2.075) 4(-2.1,1.575) 8(2.1,1.575) 9(2.1,2.075) 10(2.1,2.575)
  round 0.394 smd paste+0 mask+0: 5(-1.969,-1.335) 7(1.969,-1.335)
  rrect8% 2.35x1.33 smd paste-1000 mask+0: 6(-0.225,1.985)
  round 1.603 smd paste-1000 mask+0: 6(-0.059,-2.453)
  rrect5% 1.9x1.976 smd paste-1000 mask+0: 6(0,0.032)
  rrect40% 0.25x0.7 smd paste+0 mask+0: 12(0.825,3.35) 13(0.325,3.35) 14(-0.175,3.35) 15(-0.675,3.35) 16(-1.175,3.35)
  Top Layer region: -2.075,0.542 -2.1,0.535 -2.118,0.517 -2.125,0.492 -2.125,0.492 -2.125,0.338 -2.129,0.319 -2.14,0.303 -2.156,0.292 -2.175,0.288 -2.175,0.288 -2.4,0.288 -2.425,0.281 -2.443,0.263 -2.45,0.238 -2.45,0.238 -2.45,0.088 -2.443,0.063 -2.425,0.045 -2.4,0.038 -2.4,0.038 -2.175,0.038 -2.15,0.031 -2.132,0.013 -2.125,-0.012 -2.125,-0.012 -2.125,-0.162 -2.132,-0.187 -2.15,-0.205 -2.175,-0.212 -2.175,-0.212 -2.4,-0.212 -2.419,-0.216 -2.435,-0.227 -2.446,-0.243 -2.45,-0.262 -2.45,-0.262 -2.45,-0.412 -2.443,-0.437 -2.425,-0.455 -2.4,-0.462 -2.4,-0.462 -2.175,-0.462 -2.156,-0.466 -2.14,-0.477 -2.129,-0.493 -2.125,-0.512 -2.125,-0.512 -2.125,-0.662 -2.129,-0.681 -2.14,-0.697 -2.156,-0.708 -2.175,-0.712 -2.175,-0.712 -2.4,-0.712 -2.419,-0.716 -2.435,-0.727 -2.446,-0.743 -2.45,-0.762 -2.45,-0.762 -2.45,-0.912 -2.443,-0.937 -2.425,-0.955 -2.4,-0.962 -2.4,-0.962 -2.175,-0.962 -2.156,-0.966 -2.14,-0.977 -2.129,-0.993 -2.125,-1.012 -2.125,-1.012 -2.125,-1.162 -2.129,-1.181 -2.14,-1.197 -2.156,-1.208 -2.175,-1.212 -2.175,-1.212 -2.4,-1.212 -2.419,-1.216 -2.435,-1.227 -2.446,-1.243 -2.45,-1.262 -2.45,-1.262 -2.45,-1.412 -2.443,-1.437 -2.425,-1.455 -2.4,-1.462 -2.4,-1.462 -2.175,-1.462 -2.156,-1.466 -2.14,-1.477 -2.129,-1.493 -2.125,-1.512 -2.125,-1.512 -2.125,-1.662 -2.129,-1.681 -2.14,-1.697 -2.156,-1.708 -2.175,-1.712 -2.175,-1.712 -2.4,-1.712 -2.419,-1.716 -2.435,-1.727 -2.446,-1.743 -2.45,-1.762 -2.45,-1.762 -2.45,-1.912 -2.443,-1.937 -2.425,-1.955 -2.4,-1.962 -2.4,-1.962 -2.175,-1.962 -2.156,-1.966 -2.14,-1.977 -2.129,-1.993 -2.125,-2.012 -2.125,-2.012 -2.125,-2.162 -2.129,-2.181 -2.14,-2.197 -2.156,-2.208 -2.175,-2.212 -2.175,-2.212 -2.4,-2.212 -2.419,-2.216 -2.435,-2.227 -2.446,-2.243 -2.45,-2.262 -2.45,-2.262 -2.45,-2.412 -2.443,-2.437 -2.425,-2.455 -2.4,-2.462 -2.4,-2.462 -2.175,-2.462 -2.156,-2.466 -2.14,-2.477 -2.129,-2.493 -2.125,-2.512 -2.125,-2.512 -2.125,-2.662 -2.129,-2.681 -2.14,-2.697 -2.156,-2.708 -2.175,-2.712 -2.175,-2.712 -2.4,-2.712 -2.419,-2.716 -2.435,-2.727 -2.446,-2.743 -2.45,-2.762 -2.45,-2.762 -2.45,-2.912 -2.443,-2.937 -2.425,-2.955 -2.4,-2.962 -2.4,-2.962 -2.175,-2.962 -2.156,-2.966 -2.14,-2.977 -2.129,-2.993 -2.125,-3.012 -2.125,-3.012 -2.125,-3.166 -2.118,-3.191 -2.1,-3.209 -2.075,-3.216 -2.075,-3.216 -1.8,-3.216 -1.781,-3.212 -1.765,-3.201 -1.754,-3.185 -1.75,-3.166 -1.75,-3.166 -1.75,0.492 -1.754,0.511 -1.765,0.527 -1.781,0.538 -1.8,0.542 -1.8,0.542
  Top Layer region: 2.075,0.542 2.094,0.538 2.11,0.527 2.121,0.511 2.125,0.492 2.125,0.492 2.125,0.338 2.129,0.319 2.14,0.303 2.156,0.292 2.175,0.288 2.175,0.288 2.4,0.288 2.419,0.284 2.435,0.273 2.446,0.257 2.45,0.238 2.45,0.238 2.45,0.088 2.443,0.063 2.425,0.045 2.4,0.038 2.4,0.038 2.175,0.038 2.156,0.034 2.14,0.023 2.129,0.007 2.125,-0.012 2.125,-0.012 2.125,-0.162 2.132,-0.187 2.15,-0.205 2.175,-0.212 2.175,-0.212 2.4,-0.212 2.425,-0.219 2.443,-0.237 2.45,-0.262 2.45,-0.262 2.45,-0.412 2.446,-0.431 2.435,-0.447 2.419,-0.458 2.4,-0.462 2.4,-0.462 2.175,-0.462 2.156,-0.466 2.14,-0.477 2.129,-0.493 2.125,-0.512 2.125,-0.512 2.125,-0.662 2.129,-0.681 2.14,-0.697 2.156,-0.708 2.175,-0.712 2.175,-0.712 2.4,-0.712 2.419,-0.716 2.435,-0.727 2.446,-0.743 2.45,-0.762 2.45,-0.762 2.45,-0.912 2.446,-0.931 2.435,-0.947 2.419,-0.958 2.4,-0.962 2.4,-0.962 2.175,-0.962 2.156,-0.966 2.14,-0.977 2.129,-0.993 2.125,-1.012 2.125,-1.012 2.125,-1.162 2.129,-1.181 2.14,-1.197 2.156,-1.208 2.175,-1.212 2.175,-1.212 2.4,-1.212 2.419,-1.216 2.435,-1.227 2.446,-1.243 2.45,-1.262 2.45,-1.262 2.45,-1.412 2.446,-1.431 2.435,-1.447 2.419,-1.458 2.4,-1.462 2.4,-1.462 2.175,-1.462 2.156,-1.466 2.14,-1.477 2.129,-1.493 2.125,-1.512 2.125,-1.512 2.125,-1.662 2.129,-1.681 2.14,-1.697 2.156,-1.708 2.175,-1.712 2.175,-1.712 2.4,-1.712 2.419,-1.716 2.435,-1.727 2.446,-1.743 2.45,-1.762 2.45,-1.762 2.45,-1.912 2.446,-1.931 2.435,-1.947 2.419,-1.958 2.4,-1.962 2.4,-1.962 2.175,-1.962 2.156,-1.966 2.14,-1.977 2.129,-1.993 2.125,-2.012 2.125,-2.012 2.125,-2.162 2.129,-2.181 2.14,-2.197 2.156,-2.208 2.175,-2.212 2.175,-2.212 2.4,-2.212 2.419,-2.216 2.435,-2.227 2.446,-2.243 2.45,-2.262 2.45,-2.262 2.45,-2.412 2.446,-2.431 2.435,-2.447 2.419,-2.458 2.4,-2.462 2.4,-2.462 2.175,-2.462 2.156,-2.466 2.14,-2.477 2.129,-2.493 2.125,-2.512 2.125,-2.512 2.125,-2.662 2.129,-2.681 2.14,-2.697 2.156,-2.708 2.175,-2.712 2.175,-2.712 2.4,-2.712 2.419,-2.716 2.435,-2.727 2.446,-2.743 2.45,-2.762 2.45,-2.762 2.45,-2.912 2.446,-2.931 2.435,-2.947 2.419,-2.958 2.4,-2.962 2.4,-2.962 2.175,-2.962 2.156,-2.966 2.14,-2.977 2.129,-2.993 2.125,-3.012 2.125,-3.012 2.125,-3.166 2.121,-3.185 2.11,-3.201 2.094,-3.212 2.075,-3.216 2.075,-3.216 1.8,-3.216 1.775,-3.209 1.757,-3.191 1.75,-3.166 1.75,-3.166 1.75,0.492 1.754,0.511 1.765,0.527 1.781,0.538 1.8,0.542 1.8,0.542
  Top Layer region: -0.55,-3.65 -0.554,-3.669 -0.565,-3.685 -0.581,-3.696 -0.6,-3.7 -0.6,-3.7 -0.75,-3.7 -0.775,-3.693 -0.793,-3.675 -0.8,-3.65 -0.8,-3.65 -0.8,-3.425 -0.804,-3.406 -0.815,-3.39 -0.831,-3.379 -0.85,-3.375 -0.85,-3.375 -0.9,-3.375 -0.925,-3.368 -0.943,-3.35 -0.95,-3.325 -0.95,-3.325 -0.95,-1.506 -0.943,-1.481 -0.925,-1.463 -0.9,-1.456 -0.9,-1.456 0.9,-1.456 0.919,-1.46 0.935,-1.471 0.946,-1.487 0.95,-1.506 0.95,-1.506 0.95,-3.325 0.943,-3.35 0.925,-3.368 0.9,-3.375 0.9,-3.375 0.5,-3.375 0.481,-3.379 0.465,-3.39 0.454,-3.406 0.45,-3.425 0.45,-3.425 0.45,-3.65 0.443,-3.675 0.425,-3.693 0.4,-3.7 0.4,-3.7 0.25,-3.7 0.231,-3.696 0.215,-3.685 0.204,-3.669 0.2,-3.65 0.2,-3.65 0.2,-3.425 0.196,-3.406 0.185,-3.39 0.169,-3.379 0.15,-3.375 0.15,-3.375 0,-3.375 -0.019,-3.379 -0.035,-3.39 -0.046,-3.406 -0.05,-3.425 -0.05,-3.425 -0.05,-3.65 -0.054,-3.669 -0.065,-3.685 -0.081,-3.696 -0.1,-3.7 -0.1,-3.7 -0.25,-3.7 -0.275,-3.693 -0.293,-3.675 -0.3,-3.65 -0.3,-3.65 -0.3,-3.425 -0.304,-3.406 -0.315,-3.39 -0.331,-3.379 -0.35,-3.375 -0.35,-3.375 -0.5,-3.375 -0.519,-3.379 -0.535,-3.39 -0.546,-3.406 -0.55,-3.425 -0.55,-3.425
  Top Layer region: -2.4,2.95 -2.419,2.954 -2.435,2.965 -2.446,2.981 -2.45,3 -2.45,3 -2.45,3.15 -2.443,3.175 -2.425,3.193 -2.4,3.2 -2.4,3.2 -2.05,3.2 -2.031,3.204 -2.015,3.215 -2.004,3.231 -2,3.25 -2,3.25 -2,3.65 -1.993,3.675 -1.975,3.693 -1.95,3.7 -1.95,3.7 -1.8,3.7 -1.781,3.696 -1.765,3.685 -1.754,3.669 -1.75,3.65 -1.75,3.65 -1.75,3 -1.754,2.981 -1.765,2.965 -1.781,2.954 -1.8,2.95 -1.8,2.95
  Top Layer region: 2.4,2.95 2.419,2.954 2.435,2.965 2.446,2.981 2.45,3 2.45,3 2.45,3.15 2.446,3.169 2.435,3.185 2.419,3.196 2.4,3.2 2.4,3.2 2.05,3.2 2.025,3.207 2.007,3.225 2,3.25 2,3.25 2,3.65 1.996,3.669 1.985,3.685 1.969,3.696 1.95,3.7 1.95,3.7 1.8,3.7 1.781,3.696 1.765,3.685 1.754,3.669 1.75,3.65 1.75,3.65 1.75,3 1.754,2.981 1.765,2.965 1.781,2.954 1.8,2.95 1.8,2.95
  silkscreen extent -3.12,-3.88 2.63,3.88, body extent -2.55,-3.8 2.55,3.8, height 0.25
WE-HCM_1390_L12.5W13H9 [mm] "SMT High Current Flat Wire Inductor, 2-Leads, body 12.5x13mm"
  rect 2.5x5 smd: 1(-6.25,0) 2(6.25,0)
  silkscreen extent -6.5,-6.75 6.5,6.75, body extent -7,-6.5 7,6.5, height 9.03
WE-MAIA_3015 [mm] "SMD Power Inductor, 2-leads, body 3x3mm"
  rect 1.3x3.4 smd: 1(-1.05,0) 2(1.05,0)
  body extent -1.5,-1.5 1.5,1.5, height 1.5
WE-PD_7332_PlasticBase [mm] "SMD Inductor, 2-Leads, Body 7,3x7,3mm"
  rect 2x1.7 smd: 1(-3,0) 2(3,0)
  silkscreen extent -3.8,-3.8 3.8,3.8, body extent -3.65,-3.65 3.65,3.65, height 3.19
WEEE_Minimum [mm] "WEEElie bin"
  silkscreen extent -2.42,-4.38 2.52,2.65
WL-SMCW_GREEN [mm] "WURTH"
  rect 0.8x0.8 smd: 1(-0.8,0) 2(0.8,0)
  silkscreen extent -1.9,-0.8 1.2,0.8, body extent -0.85,-0.45 0.85,0.45, height 0.8
WL-SMCW_RED [mm] "WURTH"
  rect 0.8x0.8 smd: 1(-0.8,0) 2(0.8,0)
  silkscreen extent -1.9,-0.8 1.2,0.8, body extent -0.85,-0.45 0.85,0.45, height 0.8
